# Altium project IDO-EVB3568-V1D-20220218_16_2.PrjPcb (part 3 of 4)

## Sheet P16.SchDoc
size 297 x 209 mm
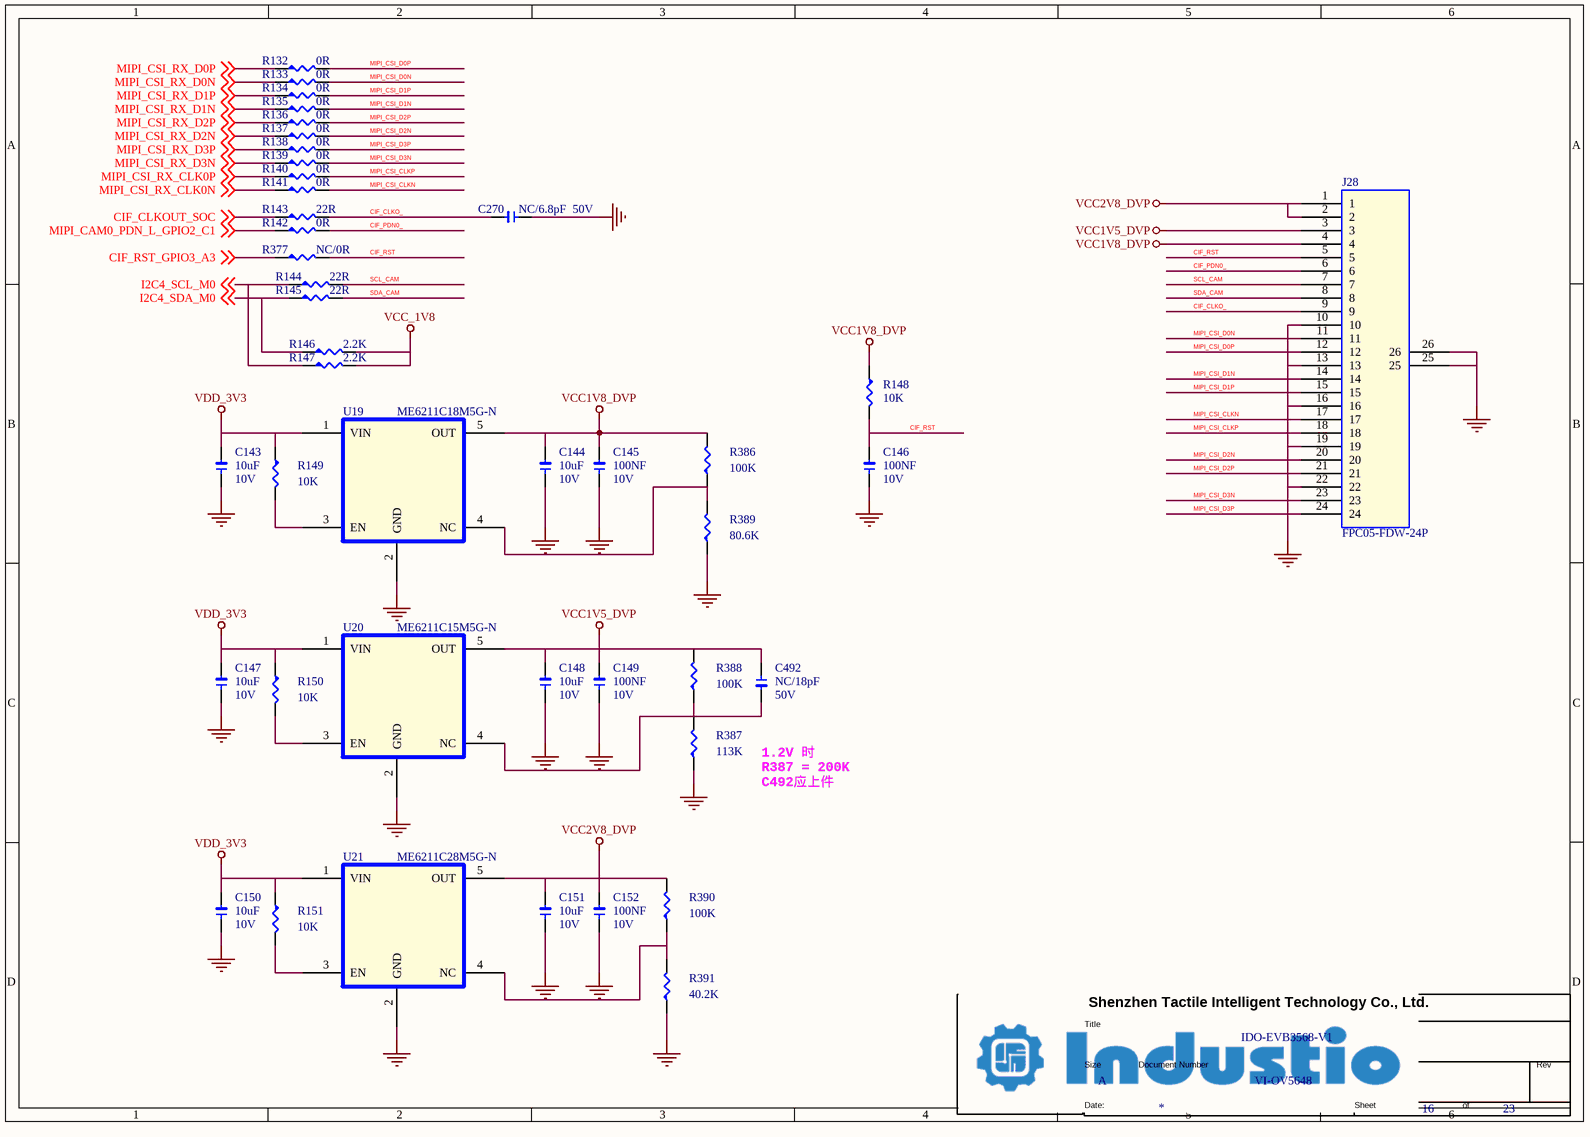
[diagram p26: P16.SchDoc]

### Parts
(Parts that share a designator on the sheet are numbered #1, #2 ... from top to bottom, then left to right.)
*#16  Doc: VI-OV5648  Title: IDO-EVB3568-V1  Page Size: A  Page Number: 16  Page Count: 23  (hidden comment: TitleBlock1)  (graphical)
C143  10uF  DSC2: 10V  [1206]
C144  10uF  DSC2: 10V  [1206]
C145  100NF  DSC2: 10V  [1206]
C146  100NF  DSC2: 10V  [1206]
C147  10uF  DSC2: 10V  [1206]
C148  10uF  DSC2: 10V  [1206]
C149  100NF  DSC2: 10V  [1206]
C150  10uF  DSC2: 10V  [1206]
C151  10uF  DSC2: 10V  [1206]
C152  100NF  DSC2: 10V  [1206]
C270  NC/6.8pF  DSC2: 50V  [1206]
C492  NC/18pF  DSC2: 50V  [1206]
J28  FPC05-FDW-24P  [FPC05-ZDW-24P]
R132  0R  [R0402L]
R133  0R  [R0402L]
R134  0R  [R0402L]
R135  0R  [R0402L]
R136  0R  [R0402L]
R137  0R  [R0402L]
R138  0R  [R0402L]
R139  0R  [R0402L]
R140  0R  [R0402L]
R141  0R  [R0402L]
R142  0R  [R0402L]
R143  22R  [R0402L]
R144  22R  [R0402L]
R145  22R  [R0402L]
R146  2.2K  [R0402L]
R147  2.2K  [R0402L]
R148  10K  [R0402L]
R149  10K  [R0402L]
R150  10K  [R0402L]
R151  10K  [R0402L]
R377  NC/0R  [R0402L]
R386  100K  [R0402L]
R387  113K  [R0402L]
R388  100K  [R0402L]
R389  80.6K  [R0402L]
R390  100K  [R0402L]
R391  40.2K  [R0402L]
U19  ME6211C18M5G-N  [SOT23-5]
U20  ME6211C15M5G-N  [SOT23-5]
U21  ME6211C28M5G-N  [SOT23-5]

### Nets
GND: C143.1 C144.1 C145.1 C146.1 C147.1 C148.1 C149.1 C150.1 C151.1 C152.1 C270.1 J28.10 J28.13 J28.16 J28.19 J28.22 J28.25 J28.26 R387.1 R389.1 R391.1 U19.2(GND) U20.2(GND) U21.2(GND)
VCC1V5_DVP: C148.2 C149.2 C492.1 J28.3 R388.2 U20.5(OUT)
VCC1V8_DVP: C144.2 C145.2 J28.4 R148.1 R386.2 U19.5(OUT)
VCC2V8_DVP: C151.2 C152.2 J28.1 J28.2 R390.2 U21.5(OUT)
VCC_1V8: R146.2 R147.2
VDD_3V3: C143.2 C147.2 C150.2 R149.1 R150.1 R151.1 U19.1(VIN) U20.1(VIN) U21.1(VIN)
CIF_CLKO_: C270.2 J28.9 R143.2
CIF_CLKOUT_SOC: R143.1 ; off-sheet CIF_CLKOUT_SOC  [project net CIF_CLKOUT/EBC_GDCLK/PWM11_IR_M1/GPIO4_C0_d]
CIF_PDN0_: J28.6 R142.2
CIF_RST: C146.2 J28.5 R148.2 R377.2
CIF_RST_GPIO3_A3: R377.1 ; off-sheet CIF_RST_GPIO3_A3  [project net LCDC_D10/VOP_BT1120_D2/GMAC1_TXD3_M0/I2S3_SCLK_M0/SDMMC2_D2_M1/GPIO3_A3_d]
I2C4_SCL_M0: R144.1 R147.1 ; off-sheet I2C4_SCL_M0  [project net I2C4_SCL_M0/EBC_GDOE/ETH1_REFCLKO_25M_M1/SPI3_CLK_M0/I2S2_SDO_M1/GPIO4_B3_d]
I2C4_SDA_M0: R145.1 R146.1 ; off-sheet I2C4_SDA_M0  [project net I2C4_SDA_M0/EBC_VCOM/GMAC1_RXER_M1/SPI3_MOSI_M0/I2S2_SDI_M1/GPIO4_B2_d]
MIPI_CAM0_PDN_L_GPIO2_C1: R142.1 ; off-sheet MIPI_CAM0_PDN_L_GPIO2_C1  [project net I2S2_MCLK_M0/ETH0_REFCLKO_25M/UART7_RTSn_M0/SPI2_CLK_M0/GPIO2_C1_d]
MIPI_CSI_CLKN: J28.17 R141.2
MIPI_CSI_CLKP: J28.18 R140.2
MIPI_CSI_D0N: J28.11 R133.2
MIPI_CSI_D0P: J28.12 R132.2
MIPI_CSI_D1N: J28.14 R135.2
MIPI_CSI_D1P: J28.15 R134.2
MIPI_CSI_D2N: J28.20 R137.2
MIPI_CSI_D2P: J28.21 R136.2
MIPI_CSI_D3N: J28.23 R139.2
MIPI_CSI_D3P: J28.24 R138.2
MIPI_CSI_RX_CLK0N: R141.1 ; off-sheet MIPI_CSI_RX_CLK0N  [project net MIPI_CSI_RX_CLK0N/PCIE30_REFCLKN_IN]
MIPI_CSI_RX_CLK0P: R140.1 ; off-sheet MIPI_CSI_RX_CLK0P  [project net MIPI_CSI_RX_CLK0P/PCIE30_REFCLKP_IN]
MIPI_CSI_RX_D0N: R133.1 ; off-sheet MIPI_CSI_RX_D0N  [project net MIPI_CSI_RX_D0N/PCIE30_TX0N]
MIPI_CSI_RX_D0P: R132.1 ; off-sheet MIPI_CSI_RX_D0P  [project net MIPI_CSI_RX_D0P/PCIE30_TX0P]
MIPI_CSI_RX_D1N: R135.1 ; off-sheet MIPI_CSI_RX_D1N  [project net MIPI_CSI_RX_D1N/PCIE30_TX1N]
MIPI_CSI_RX_D1P: R134.1 ; off-sheet MIPI_CSI_RX_D1P  [project net MIPI_CSI_RX_D1P/PCIE30_TX1P]
MIPI_CSI_RX_D2N: R137.1 ; off-sheet MIPI_CSI_RX_D2N  [project net MIPI_CSI_RX_D2N/PCIE30_RX0N]
MIPI_CSI_RX_D2P: R136.1 ; off-sheet MIPI_CSI_RX_D2P  [project net MIPI_CSI_RX_D2P/PCIE30_RX0P]
MIPI_CSI_RX_D3N: R139.1 ; off-sheet MIPI_CSI_RX_D3N  [project net MIPI_CSI_RX_D3N/PCIE30_RX1N]
MIPI_CSI_RX_D3P: R138.1 ; off-sheet MIPI_CSI_RX_D3P  [project net MIPI_CSI_RX_D3P/PCIE30_RX1P]
SCL_CAM: J28.7 R144.2
SDA_CAM: J28.8 R145.2
NetC492_2: C492.2 R387.2 R388.1 U20.4(NC)
NetR149_2: R149.2 U19.3(EN)
NetR150_2: R150.2 U20.3(EN)
NetR151_2: R151.2 U21.3(EN)
NetR386_1: R386.1 R389.2 U19.4(NC)
NetR390_1: R390.1 R391.2 U21.4(NC)

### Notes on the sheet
- 1.2V 时
  R387 = 200K
  C492应上件

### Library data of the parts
C143 C144 C147 C148 C150 C151 = C-0603: Manufacture: 三星¦国巨¦村田; Part Name: 贴片电容; Part Number: C020102120071; ID: 71; DSC3: X5R; DSC1: ±20%; ERP Number: 1010200076; PCB Footprint: C0603L
C145 C146 C152 = C-0402_Dup1: Part Number: C020102120060; Part Name: 贴片电容; Manufacture: 三星¦国巨¦村田; DSC1: ±10%; DSC3: X7R; ID: 60; PCB Footprint: C0402L
C149 = C-0402_Dup1: Manufacture: 三星¦国巨¦村田; Part Name: 贴片电容; Part Number: C020102120060; ID: 60; DSC3: X7R; DSC1: ±10%; PCB Footprint: C0402L
C270 = C-0402_Dup1: Manufacture: 三星¦国巨¦村田; Part Name: 贴片电容; Part Number: C020102120018; PCB Footprint: C0402L; ID: 18; DSC3: C0G; DSC1: ±0.25PF; ERP Number: 1010200056
C492 = C-0402_Dup1: Part Number: C020102120027; Part Name: 贴片电容; Manufacture: 三星¦国巨¦村田; ERP Number: 1010200091; DSC1: ±5%; DSC3: C0G; ID: 27; PCB Footprint: C0402L
J28 = J-FPC05-24P: Part Name: FPC座; DSC1: 24P; DSC2: 0.5mm间距; DSC3: 下接 翻盖 卧贴; DSC4: H=2mm; DSC5: 镀锡; DSC6: X05C2024TZ(星坤); ID: 37
R132-R141 R377 = R-0402_Dup1: Part Number: C011002080413; Part Name: 贴片电阻; ID: 413; DSC2: 1/16W; DSC1: ±1%
R142 = R-0402_Dup1: Part Name: 贴片电阻; Part Number: C011002080413; DSC1: ±1%; DSC2: 1/16W; ID: 413
R143 = R-0402_Dup1: Part Name: 贴片电阻; Part Number: C011002080552; DSC1: ±1%; DSC2: 1/16W; ID: 552
R144 R145 = R-0402_Dup1: Part Number: C011002080552; Part Name: 贴片电阻; ID: 552; DSC2: 1/16W; DSC1: ±1%
R146 = R-0402_Dup1: Part Number: C011002080778; Part Name: 贴片电阻; ID: 778; DSC2: 1/16W; DSC1: ±1%
R147 = R-0402_Dup1: Part Name: 贴片电阻; Part Number: C011002080778; DSC1: ±1%; DSC2: 1/16W; ID: 778
R148-R151 = R-0402_Dup1: Part Number: C011002080856; Part Name: 贴片电阻; ID: 856; DSC2: 1/16W; DSC1: ±1%; ERP Number: 1010200140
R386 R388 R390 = R-0402: Part Number: C011002080976; Part Name: 贴片电阻; DSC2: 1/16W; DSC1: ±1%; ERP Number: 1010200137
R387 = R-0402: Part Number: C011002080981; Part Name: 贴片电阻; DSC2: 1/16W; DSC1: ±1%
R389 = R-0402: Part Name: 贴片电阻; Part Number: C011002080964; ERP Number: 1010200373; DSC1: ±1%; DSC2: 1/16W
R391 = R-0402: Part Name: 贴片电阻; Part Number: C011002080926; ERP Number: 1010200179; DSC1: ±1%; DSC2: 1/16W
U19 = U-ME6211C18M5G-N: Manufacture: 南京微盟; Part Number: C070102400003; Part Name: LDO; ID: 3; DSC5: Iq=30uA; DSC4: -62db(1K); DSC3: Io=500mA; DSC2: Vo=1.8V; DSC1: Vi=1.5-6.5V
U20 = U-ME6211C15M5G-N: Manufacture: 南京微盟; Part Number: C070107223911; Part Name: LDO; ID: 27; DSC5: Iq=30uA; DSC4: -62db(1K); DSC3: Io=300mA; DSC2: Vo=1.5V; DSC1: Vi=1.5-6.5V
U21 = U-ME6211C28M5G-N: Part Name: LDO; Part Number: C070102400018; Manufacture: 南京微盟; DSC1: Vi=1.5-6.5V; DSC2: Vo=2.8V; DSC3: Io=500mA; DSC4: -62db(1K); DSC5: Iq=30uA; ID: 18

## Sheet P17.SchDoc
size 420 x 297 mm
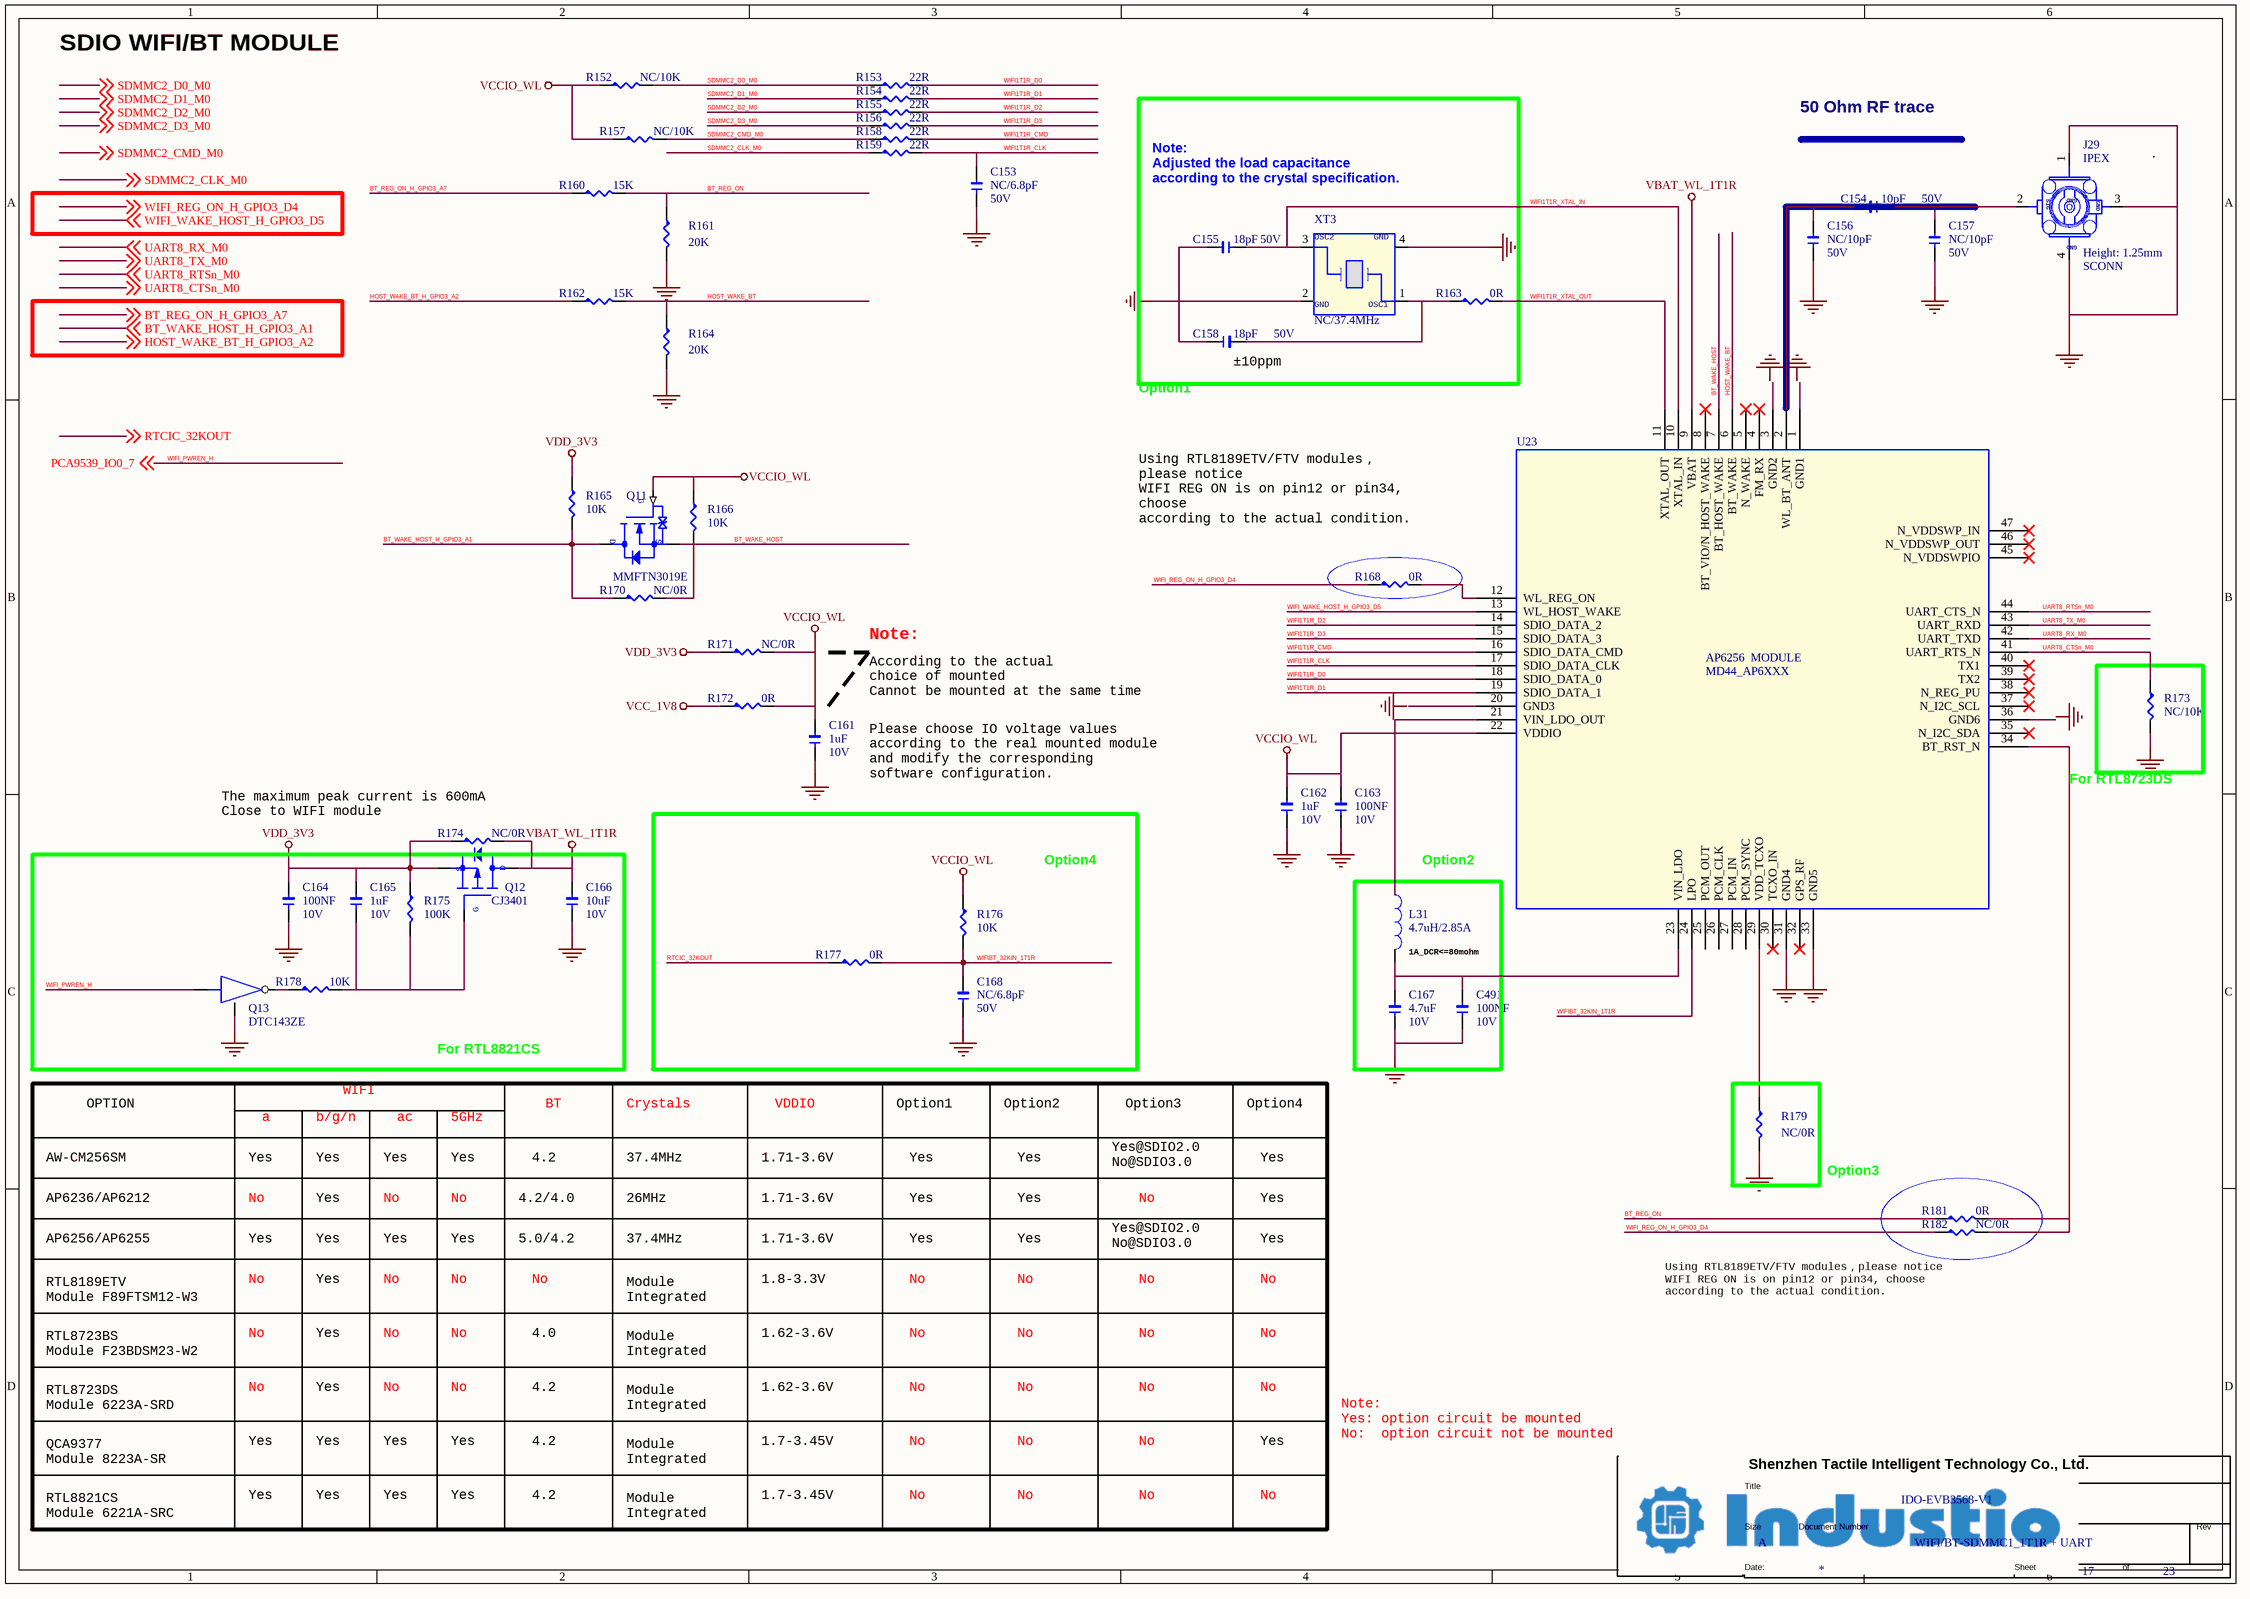
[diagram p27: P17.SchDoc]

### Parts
(Parts that share a designator on the sheet are numbered #1, #2 ... from top to bottom, then left to right.)
*#17  Doc: WIFI/BT-SDMMC1_1T1R + UART  Title: IDO-EVB3568-V1  Page Size: A  Page Number: 17  Page Count: 23  (hidden comment: TitleBlock1)  (graphical)
C153  NC/6.8pF  DSC2: 50V  [1206]
C154  10pF  DSC2: 50V  [1206]
C155  18pF  DSC2: 50V  [1206]
C156  NC/10pF  DSC2: 50V  [1206]
C157  NC/10pF  DSC2: 50V  [1206]
C158  18pF  DSC2: 50V  [1206]
C161  1uF  DSC2: 10V  [1206]
C162  1uF  DSC2: 10V  [1206]
C163  100NF  DSC2: 10V  [1206]
C164  100NF  DSC2: 10V  [1206]
C165  1uF  DSC2: 10V  [1206]
C166  10uF  DSC2: 10V  [1206]
C167  4.7uF  DSC2: 10V  [1206]
C168  NC/6.8pF  DSC2: 50V  [1206]
C491  100NF  DSC2: 10V  [1206]
J29  IPEX  Height: 1.25mm  Material: SCONN  [IPEX-20279-001E]
L31  4.7uH/2.85A  [L4040]
Q11  MMFTN3019E  [SOT523]
Q12  CJ3401  [SOT23]
Q13  DTC143ZE  [SOT523]
R152  NC/10K  [R0402L]
R153  22R  [R0402L]
R154  22R  [R0402L]
R155  22R  [R0402L]
R156  22R  [R0402L]
R157  NC/10K  [R0402L]
R158  22R  [R0402L]
R159  22R  [R0402L]
R160  15K  [R0402L]
R161  20K  [R0402L]
R162  15K  [R0402L]
R163  0R  [R0402L]
R164  20K  [R0402L]
R165  10K  [R0402L]
R166  10K  [R0402L]
R168  0R  [R0402L]
R170  NC/0R  [R0402L]
R171  NC/0R  [R0402L]
R172  0R  [R0402L]
R173  NC/10K  [R0402L]
R174  NC/0R  [R0805L]
R175  100K  [R0402L]
R176  10K  [R0402L]
R177  0R  [R0402L]
R178  10K  [R0402L]
R179  NC/0R  [R0402L]
R181  0R  [R0402L]
R182  NC/0R  [R0402L]
U23  AP6256  MODULE  [MD44_AP6XXX]
XT3  NC/37.4MHz  [xtal_32x25_4p]

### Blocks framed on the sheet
±10ppm: C155 C158 R163 XT3
For RTL8821CS: C164-C166 Q12 Q13 R175 R178
Option4: C168 R176 R177
Option2: C167 C491 L31

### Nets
GND: C153.1 C155.2 C156.1 C157.1 C158.1 C161.1 C162.1 C163.1 C164.1 C166.1 C167.1 C168.1 C491.1 J29.1(GND1) J29.3(GND2) J29.4(GND3) Q13.2 R161.2 R164.2 R173.2 R179.2 U23.31(GND4) U23.33(GND5) XT3.2 XT3.4
VBAT_WL_1T1R: C166.2 Q12.3(DRAIN) R174.2 U23.9(VBAT)
VCC_1V8: R172.1
VCCIO_WL: C161.2 C162.2 C163.2 Q11.1(GATE) R152.1 R157.1 R166.1 R171.2 R172.2 R176.1 U23.22(VDDIO)
VDD_3V3: C164.2 C165.2 Q12.2(SOURCE) R165.1 R171.1 R174.1 R175.1
BT_REG_ON: R160.2 R161.1 R181.1
BT_REG_ON_H_GPIO3_A7: R160.1 ; off-sheet BT_REG_ON_H_GPIO3_A7
BT_WAKE_HOST: Q11.2(SOURCE) R166.2 R170.2 U23.7(BT_HOST_WAKE)
BT_WAKE_HOST_H_GPIO3_A1: Q11.3(DRAIN) R165.2 R170.1 ; off-sheet BT_WAKE_HOST_H_GPIO3_A1
HOST_WAKE_BT: R162.2 R164.1 U23.6(BT_WAKE)
HOST_WAKE_BT_H_GPIO3_A2: R162.1 ; off-sheet HOST_WAKE_BT_H_GPIO3_A2
PCA9539_IO0_7: Q13.1 ; off-sheet PCA9539_IO0_7  [also labelled WIFI_PWREN_H]
RTCIC_32KOUT: R177.1 ; off-sheet RTCIC_32KOUT  [project net RTC_32KOUT]
SDMMC2_CLK_M0: R159.1 ; off-sheet SDMMC2_CLK_M0  [project net CIF_D5/EBC_SDDO5/SDMMC2_CLK_M0/I2S1_SDI1_M1/VOP_BT656_D5_M1/GPIO3_D3_d]
SDMMC2_CMD_M0: R157.2 R158.1 ; off-sheet SDMMC2_CMD_M0  [project net CIF_D4/EBC_SDDO4/SDMMC2_CMD_M0/I2S1_SDI0_M1/VOP_BT656_D4_M1/GPIO3_D2_d]
SDMMC2_D0_M0: R152.2 R153.1 ; off-sheet SDMMC2_D0_M0  [project net CIF_D0/EBC_SDDO0/SDMMC2_D0_M0/I2S1_MCLK_M1/VOP_BT656_D0_M1/GPIO3_C6_d]
SDMMC2_D1_M0: R154.1 ; off-sheet SDMMC2_D1_M0  [project net CIF_D1/EBC_SDDO1/SDMMC2_D1_M0/I2S1_SCLK_TX_M1/VOP_BT656_D1_M1/GPIO3_C7_d]
SDMMC2_D2_M0: R155.1 ; off-sheet SDMMC2_D2_M0  [project net CIF_D2/EBC_SDDO2/SDMMC2_D2_M0/I2S1_LRCK_TX_M1/VOP_BT656_D2_M1/GPIO3_D0_d]
SDMMC2_D3_M0: R156.1 ; off-sheet SDMMC2_D3_M0  [project net CIF_D3/EBC_SDDO3/SDMMC2_D3_M0/I2S1_SDO0_M1/VOP_BT656_D3_M1/GPIO3_D1_d]
UART8_CTSn_M0: R173.1 U23.41(UART_RTS_N) ; off-sheet UART8_CTSn_M0  [project net SDMMC1_DET/I2C4_SCL_M1/UART8_CTSn_M0/CAN2_TX_M1/GPIO2_B2_u]
UART8_RTSn_M0: U23.44(UART_CTS_N) ; off-sheet UART8_RTSn_M0  [project net SDMMC1_PWREN/I2C4_SDA_M1/UART8_RTSn_M0/CAN2_RX_M1/GPIO2_B1_d]
UART8_RX_M0: U23.42(UART_TXD) ; off-sheet UART8_RX_M0  [project net CLK32K_OUT1/UART8_RX_M0/SPI1_CS1_M0/GPIO2_C6_d]
UART8_TX_M0: U23.43(UART_RXD) ; off-sheet UART8_TX_M0  [project net I2S2_SDI_M0/GMAC0_RXER/UART8_TX_M0/SPI2_CS1_M0/GPIO2_C5_d]
WIFI1T1R_CLK: C153.2 R159.2 U23.17(SDIO_DATA_CLK)
WIFI1T1R_CMD: R158.2 U23.16(SDIO_DATA_CMD)
WIFI1T1R_D0: R153.2 U23.18(SDIO_DATA_0)
WIFI1T1R_D1: R154.2 U23.19(SDIO_DATA_1)
WIFI1T1R_D2: R155.2 U23.14(SDIO_DATA_2)
WIFI1T1R_D3: R156.2 U23.15(SDIO_DATA_3)
WIFI1T1R_XTAL_IN: C155.1 U23.10(XTAL_IN) XT3.3
WIFI1T1R_XTAL_OUT: R163.2 U23.11(XTAL_OUT)
WIFI_REG_ON_H_GPIO3_D4: R168.1 R182.1 ; off-sheet WIFI_REG_ON_H_GPIO3_D4  [project net CIF_D6/EBC_SDDO6/SDMMC2_DET_M0/I2S1_SDI2_M1/VOP_BT656_D6_M1/GPIO3_D4_d]
WIFI_WAKE_HOST_H_GPIO3_D5: U23.13(WL_HOST_WAKE) ; off-sheet WIFI_WAKE_HOST_H_GPIO3_D5  [project net CIF_D7/EBC_SDDO7/SDMMC2_PWREN_M0/I2S1_SDI3_M1/VOP_BT656_D7_M1/GPIO3_D5_d]
WIFIBT_32KIN_1T1R: C168.2 R176.2 R177.2 U23.24(LPO)
NetC154_1: C154.1 C157.2 J29.2(SIG)
NetC154_2: C154.2 C156.2 U23.2(WL_BT_ANT)
NetC158_2: C158.2 R163.1 XT3.1
NetC165_1: C165.1 Q12.1(GATE) R175.2 R178.2
NetC167_2: C167.2 C491.2 L31.2 U23.23(VIN_LDO)
NetL31_1: L31.1 U23.21(VIN_LDO_OUT)
NetQ13_3: Q13.3 R178.1
NetR168_2: R168.2 U23.12(WL_REG_ON)
NetR179_1: R179.1 U23.29(VDD_TCXO)
NetR181_2: R181.2 R182.2 U23.34(BT_RST_N)

Not connected (* = marked no-connect by the designer): U23 1(GND1) 3(GND2) 4(FM_RX)* 5(N_WAKE)* 8(BT_VIO/N_HOST_WAKE)* 20(GND3) 25(PCM_OUT) 26(PCM_CLK) 27(PCM_IN) 28(PCM_SYNC) 30(TCXO_IN)* 32(GPS_RF)* 35(N_I2C_SDA)* 36(GND6) 37(N_I2C_SCL)* 38(N_REG_PU)* 39(TX2)* 40(TX1)* 45(N_VDDSWPIO)* 46(N_VDDSWP_OUT)* 47(N_VDDSWP_IN)*

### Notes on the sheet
- SDIO WIFI/BT MODULE
- 50 Ohm RF trace
- Note:
  Adjusted the load capacitance
  according to the crystal specification.
- (near C158) Option1
- (near U23) Using RTL8189ETV/FTV modules，
  please notice
  WIFI REG ON is on pin12 or pin34,
  choose
  according to the actual condition.
- According to the actual
  choice of mounted
  Cannot be mounted at the same time
- Note:
- (near C162) Please choose IO voltage values
  according to the real mounted module
  and modify the corresponding
  software configuration.
- (near R174) The maximum peak current is 600mA
  Close to WIFI module
- For RTL8723DS
- (near L31) 1A_DCR<=80mohm
- OPTION
- a
- b/g/n
- WIFI
- ac
- 5GHz
- BT
- Crystals
- VDDIO
- Option1
- Option2
- Yes@SDIO2.0
  No@SDIO3.0
- Option3
- Option4
- AP6236/AP6212
- AW-CM256SM
- No
- Yes
- 4.2/4.0
- 4.2
- 26MHz
- 37.4MHz
- 1.71-3.6V
- AP6256/AP6255
- RTL8189ETV
  Module F89FTSM12-W3
- 5.0/4.2
- Module
  Integrated
- Using RTL8189ETV/FTV modules，please notice
  WIFI REG ON is on pin12 or pin34, choose
  according to the actual condition.
- RTL8723BS
  Module F23BDSM23-W2
- 4.0
- 1.62-3.6V
- 1.8-3.3V
- RTL8723DS
  Module 6223A-SRD
- (near *#17) Note:
  Yes: option circuit be mounted
  No:  option circuit not be mounted
- QCA9377
  Module 8223A-SR
- 1.7-3.45V
- RTL8821CS
  Module 6221A-SRC
- Labels drawn without touching a wire or pin: GND

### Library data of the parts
C153 = C-0402_Dup1: as C270 on sheet P16
C154 = C-0402_Dup1: Part Number: C020102120021; Part Name: 贴片电容; Manufacture: 三星¦国巨¦村田; PCB Footprint: C0402L; ERP Number: 1010200151; DSC1: ±5%; DSC3: C0G; ID: 21
C155 = C-0402_Dup1: as C492 on sheet P16
C156 C157 = C-0402_Dup1: Manufacture: 三星¦国巨¦村田; Part Name: 贴片电容; Part Number: C020102120021; PCB Footprint: C0402L; ID: 21; DSC3: C0G; DSC1: ±5%; ERP Number: 1010200151
C158 = C-0402_Dup1: Manufacture: 三星¦国巨¦村田; Part Name: 贴片电容; Part Number: C020102120027; ID: 27; DSC3: C0G; DSC1: ±5%; ERP Number: 1010200091; PCB Footprint: C0402L
C161 = C-0402_Dup1: Part Number: C020102120064; Part Name: 贴片电容; Manufacture: 三星¦国巨¦村田; PCB Footprint: C0402L; ERP Number: 1010200054; DSC1: ±10%; DSC3: X5R; ID: 64
C162 C165 = C-0402_Dup1: Manufacture: 三星¦国巨¦村田; Part Name: 贴片电容; Part Number: C020102120064; PCB Footprint: C0402L; ID: 64; DSC3: X5R; DSC1: ±10%; ERP Number: 1010200054
C163 C164 C491 = C-0402_Dup1: Manufacture: 三星¦国巨¦村田; Part Name: 贴片电容; Part Number: C020102120060; PCB Footprint: C0402L; ID: 60; DSC3: X7R; DSC1: ±10%
C166 = C-0603: Part Number: C020102120071; Part Name: 贴片电容; Manufacture: 三星¦国巨¦村田; PCB Footprint: C0603L; ERP Number: 1010200076; DSC1: ±20%; DSC3: X5R; ID: 71
C167 = C-0402_Dup1: Manufacture: 三星¦国巨¦村田; Part Name: 贴片电容; Part Number: C020102120067; PCB Footprint: C0402L; ID: 67; DSC3: X5R; DSC1: ±20%
C168 = C-0402_Dup1: Part Number: C020102120018; Part Name: 贴片电容; Manufacture: 三星¦国巨¦村田; PCB Footprint: C0402L; ERP Number: 1010200056; DSC1: ±0.25PF; DSC3: C0G; ID: 18
J29 = RF-IPEX-20279: SMD micro Coaxial Connector Receptacle vertial; Part_Name: MHF-20279; Part Name: IPEX座; Part Number: J110103040001; ID: 1; DSC2: 贴片; DSC1: IPEX-20279-001E-01 板端贴片天线座 U.LF接头
L31 = L-IND: Part Name: 功率电感; Part Number: C060202340021; Manufacture: 顺络; ERP Number: 1010200405; DSC1: ±20%; DSC2: Isat=4.0A; DSC3: Irms=2.85A; DSC4: 108mΩ; DSC5: 4.0*4.0*2.0mm; DSC6: WPN4020H4R7MT(顺络)
Q11 = N-MOS-Q: Manufacture: 先科; Part Name: N-MOS; Part Number: C030202190004; ID: 4; DSC5: pd=150mW; DSC4: Vgs=±20V; DSC3: Vgs(th)=1.5V; DSC2: Id=100mA; DSC1: Vds=30V; ERP Number: 1010800011
Q12 = P-MOS: Part Number: C030202190001; Manufacture: 长电; ERP Number: 1010800001; DSC1: Vds=-30V; DSC2: Id=-4.2A; DSC3: Vgs(th)=1.3V; DSC4: Vgs=±12V; DSC5: pd=350mW; ID: 1
Q13 = S-NPN: Manufacture: CJ江苏长电; Part Number: BJ00G1100000; LC Number: C78593; DSC1: 数字三极管,NPN - 预偏压,Ic=100mA; Type Name: 数字三极管; ERP Number: 0; ID: 2
R152 R157 R165 R166 = R-0402_Dup1: as R148-R151 on sheet P16
R153 = R-0402_Dup1: as R144 on sheet P16
R154-R156 R158 R159 = R-0402_Dup1: as R143 on sheet P16
R160 R162 = R-0402_Dup1: Part Number: C011002080875; Part Name: 贴片电阻; ID: 875; DSC2: 1/16W; DSC1: ±1%; ERP Number: 1010200458
R161 R164 = R-0402_Dup1: Part Number: C011002080889; Part Name: 贴片电阻; ID: 889; DSC2: 1/16W; DSC1: ±1%; ERP Number: 1010200333
R163 R172 R177 R181 R182 = R-0402_Dup1: as R132-R141 on sheet P16
R168 R170 R171 R179 = R-0402_Dup1: as R142 on sheet P16
R173 R176 R178 = R-0402_Dup1: Part Name: 贴片电阻; Part Number: C011002080856; ERP Number: 1010200140; DSC1: ±1%; DSC2: 1/16W; ID: 856
R174 = R-0805: Part Name: 贴片电阻; Part Number: C011002081448; ERP Number: 1010200199; DSC1: ±1%; DSC2: 1/8W; ID: 1,448
R175 = R-0402_Dup1: Part Name: 贴片电阻; Part Number: C011002080976; ERP Number: 1010200137; DSC1: ±1%; DSC2: 1/16W; ID: 976
U23 = MODULE_AP6XXX: WiFi+Bluetooth 4.0(HS)+FM Rx; Manufacturer: Ampak（正基科技）; RK PN: AP6335; Priority: A
XT3 = XTAL-4P: Manufacture: 爱普生; Part Name: 贴片无源晶振; CLASS: IC; ID: 13; DSC5: 3.2*2.5mm 4P; DSC4: -40℃~+85℃; DSC3: 12pF; DSC2: ±10ppm; DSC1: 60Ω

## Sheet P18.SchDoc
size 594 x 420 mm
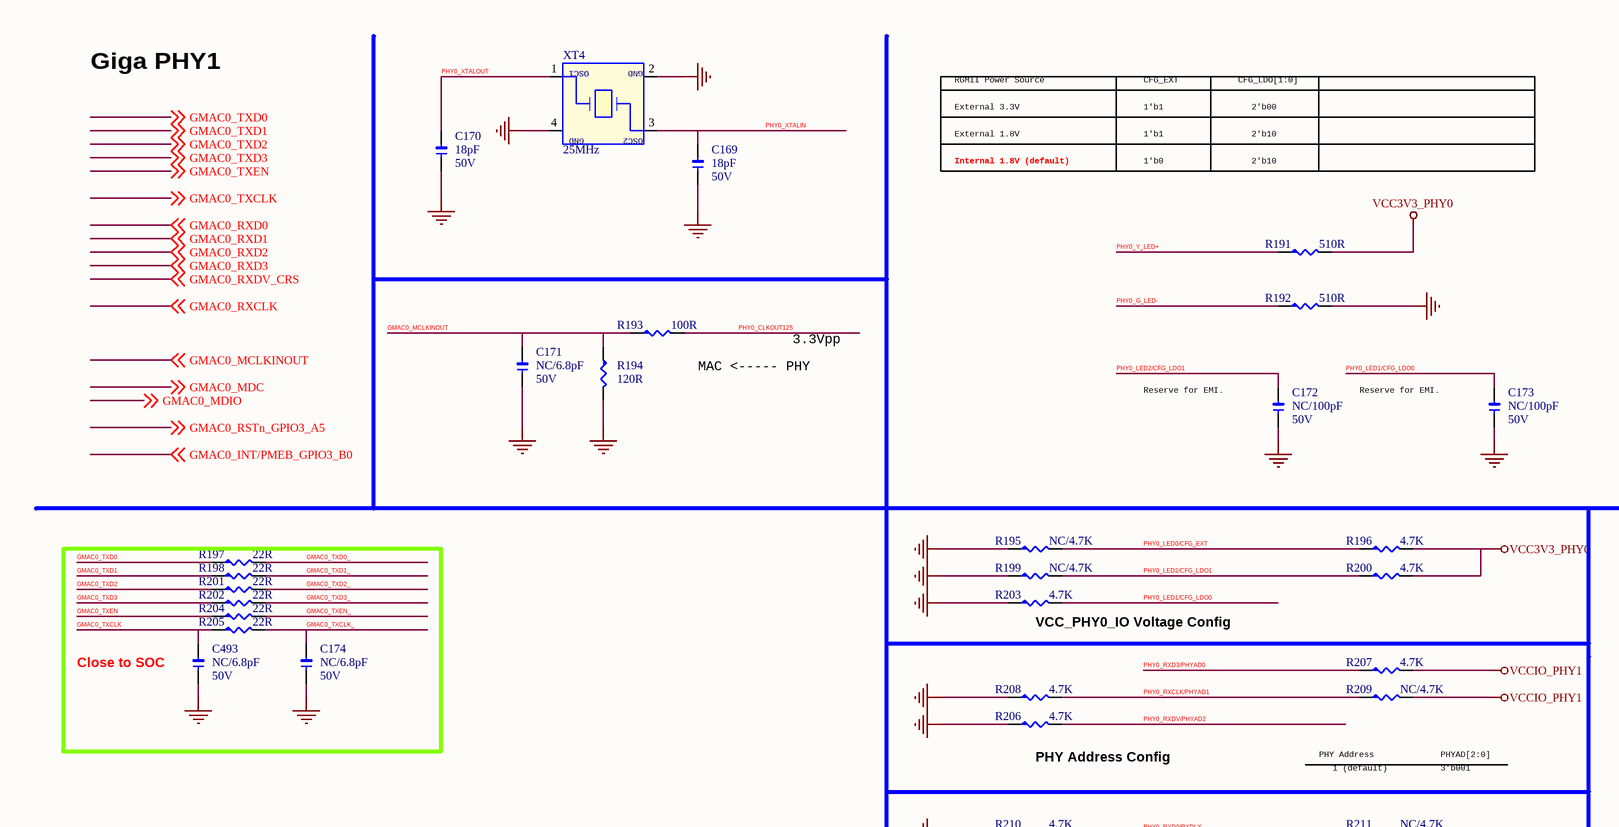
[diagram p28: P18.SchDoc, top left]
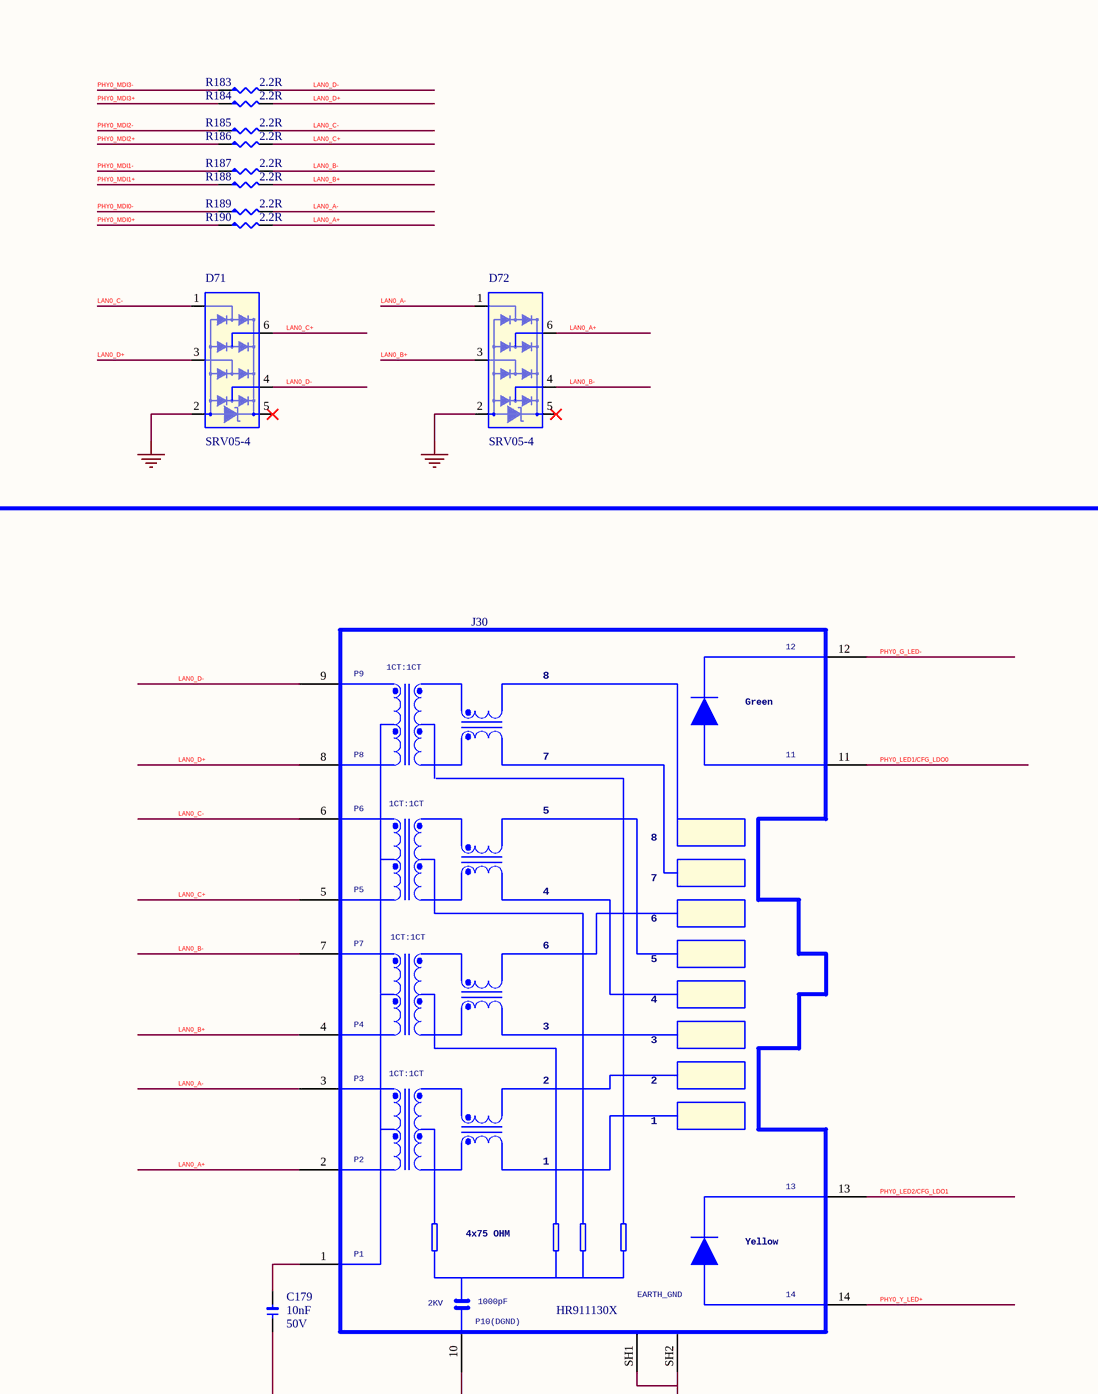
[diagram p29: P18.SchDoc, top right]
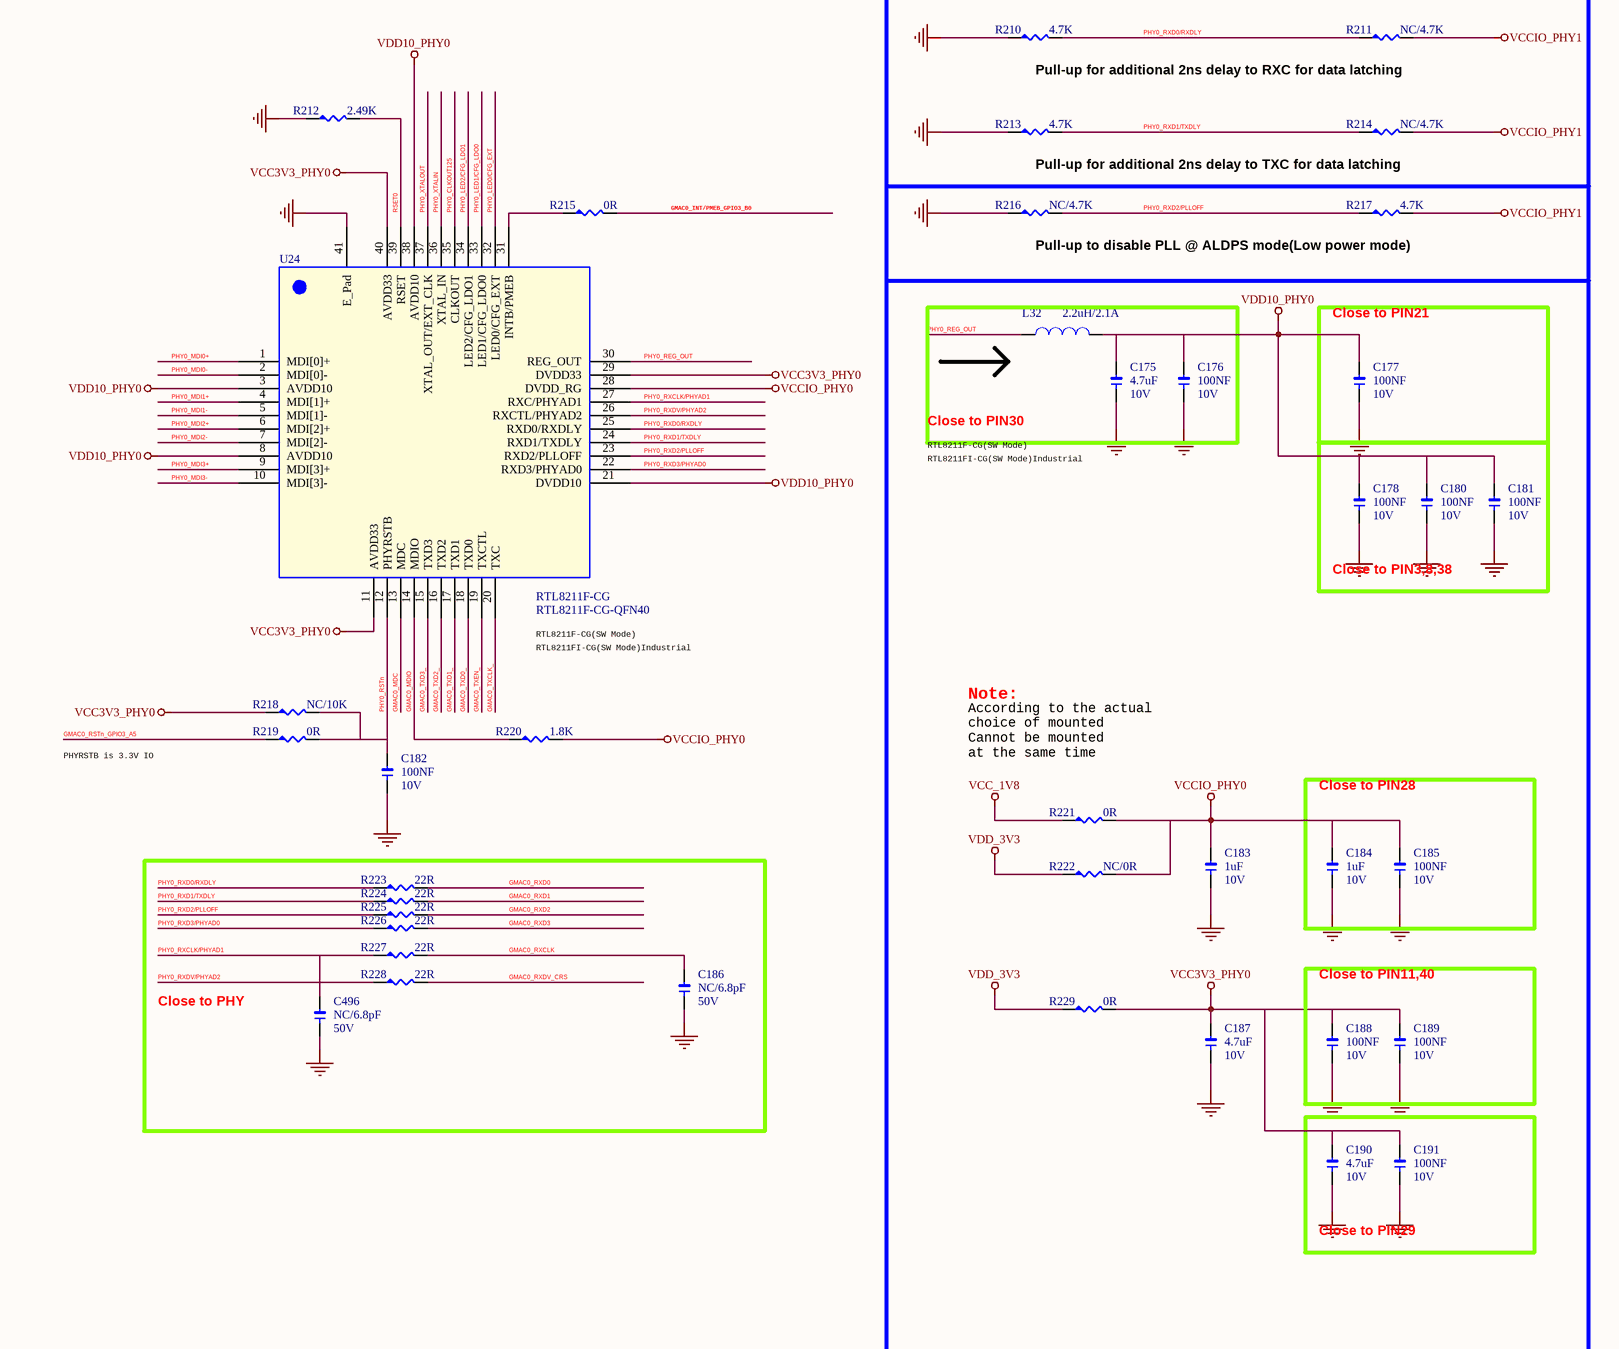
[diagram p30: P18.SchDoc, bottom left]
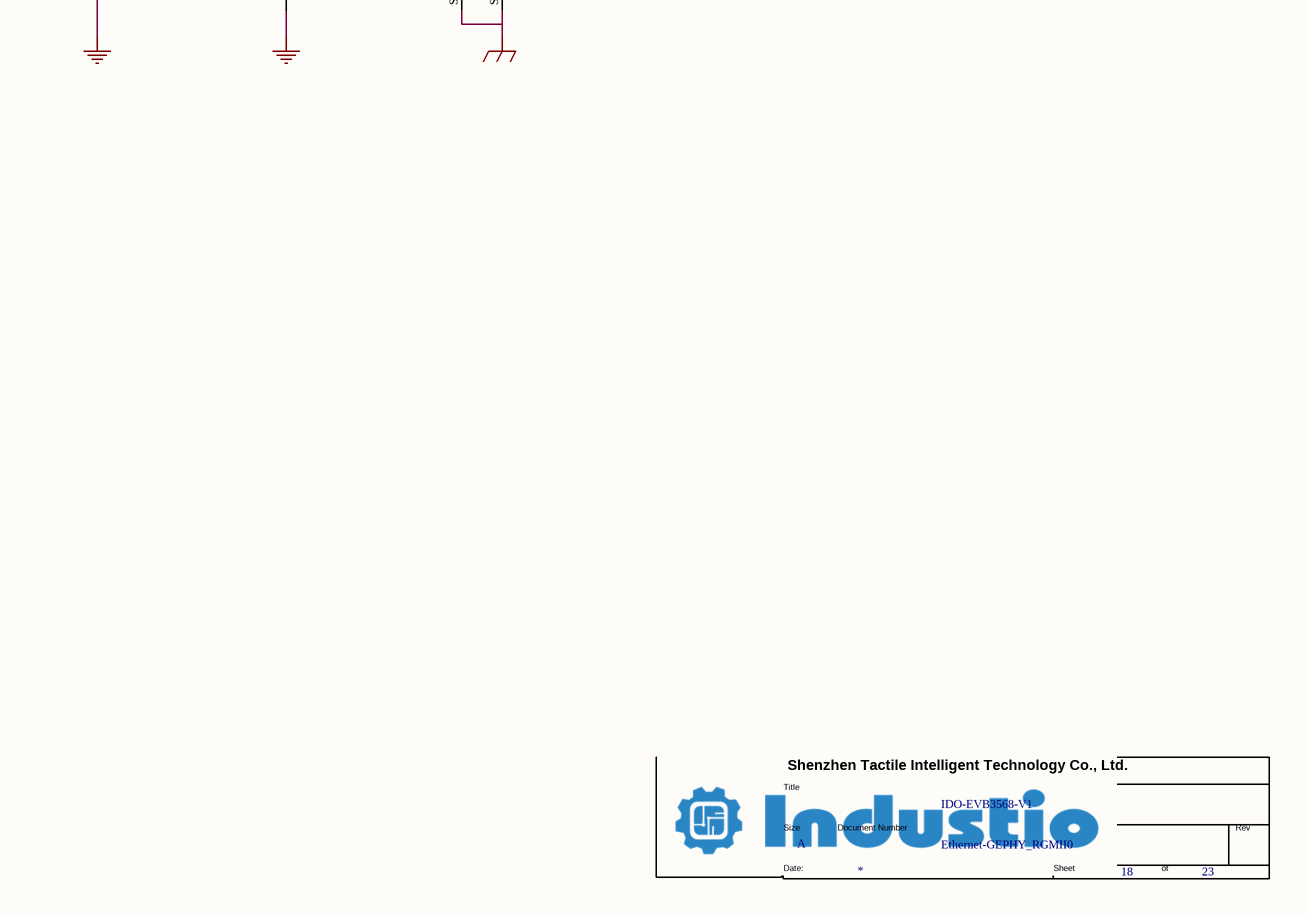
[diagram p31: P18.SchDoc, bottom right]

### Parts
(Parts that share a designator on the sheet are numbered #1, #2 ... from top to bottom, then left to right.)
*#18  Doc: Ethernet-GEPHY_RGMII0  Title: IDO-EVB3568-V1  Page Size: A  Page Number: 18  Page Count: 23  (hidden comment: TitleBlock1)  (graphical)
C169  18pF  DSC2: 50V  [1206]
C170  18pF  DSC2: 50V  [1206]
C171  NC/6.8pF  DSC2: 50V  [1206]
C172  NC/100pF  DSC2: 50V  [1206]
C173  NC/100pF  DSC2: 50V  [1206]
C174  NC/6.8pF  DSC2: 50V  [1206]
C175  4.7uF  DSC2: 10V  [1206]
C176  100NF  DSC2: 10V  [1206]
C177  100NF  DSC2: 10V  [1206]
C178  100NF  DSC2: 10V  [1206]
C179  10nF  DSC2: 50V  [1206]
C180  100NF  DSC2: 10V  [1206]
C181  100NF  DSC2: 10V  [1206]
C182  100NF  DSC2: 10V  [1206]
C183  1uF  DSC2: 10V  [1206]
C184  1uF  DSC2: 10V  [1206]
C185  100NF  DSC2: 10V  [1206]
C186  NC/6.8pF  DSC2: 50V  [1206]
C187  4.7uF  DSC2: 10V  [1206]
C188  100NF  DSC2: 10V  [1206]
C189  100NF  DSC2: 10V  [1206]
C190  4.7uF  DSC2: 10V  [1206]
C191  100NF  DSC2: 10V  [1206]
C493  NC/6.8pF  DSC2: 50V  [1206]
C496  NC/6.8pF  DSC2: 50V  [1206]
D71  SRV05-4  [SOT23-6]
D72  SRV05-4  [SOT23-6]
J30  HR911130X  [HR911130X]
L32  2.2uH/2.1A  [L2520]
R183  2.2R  [R0402L]
R184  2.2R  [R0402L]
R185  2.2R  [R0402L]
R186  2.2R  [R0402L]
R187  2.2R  [R0402L]
R188  2.2R  [R0402L]
R189  2.2R  [R0402L]
R190  2.2R  [R0402L]
R191  510R  [R0402L]
R192  510R  [R0402L]
R193  100R  [R0402L]
R194  120R  [R0402L]
R195  NC/4.7K  [R0402L]
R196  4.7K  [R0402L]
R197  22R  [R0402L]
R198  22R  [R0402L]
R199  NC/4.7K  [R0402L]
R200  4.7K  [R0402L]
R201  22R  [R0402L]
R202  22R  [R0402L]
R203  4.7K  [R0402L]
R204  22R  [R0402L]
R205  22R  [R0402L]
R206  4.7K  [R0402L]
R207  4.7K  [R0402L]
R208  4.7K  [R0402L]
R209  NC/4.7K  [R0402L]
R210  4.7K  [R0402L]
R211  NC/4.7K  [R0402L]
R212  2.49K  [R0402L]
R213  4.7K  [R0402L]
R214  NC/4.7K  [R0402L]
R215  0R  [R0402L]
R216  NC/4.7K  [R0402L]
R217  4.7K  [R0402L]
R218  NC/10K  [R0402L]
R219  0R  [R0402L]
R220  1.8K  [R0402L]
R221  0R  [R0402L]
R222  NC/0R  [R0402L]
R223  22R  [R0402L]
R224  22R  [R0402L]
R225  22R  [R0402L]
R226  22R  [R0402L]
R227  22R  [R0402L]
R228  22R  [R0402L]
R229  0R  [R0402L]
U24  RTL8211F-CG  PCB Footprint: RTL8211F-CG-QFN40  [QFN40_5R00X5R00X0R80_T]
XT4  25MHz  [xtal_32x25_4p]

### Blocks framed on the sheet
Close to SOC: C174 C493 R197 R198 R201 R202 R204 R205
Close to PIN30: C175 C176 L32
Close to PIN21: C177
Close to PIN3,8,38: C178 C180 C181
Close to PIN28: C184 C185
Close to PHY: C186 C496 R223-R228
Close to PIN11,40: C188 C189
Close to PIN29: C190 C191

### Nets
GND: C169.1 C170.1 C171.1 C172.1 C173.1 C174.1 C175.1 C176.1 C177.1 C178.1 C179.1 C180.1 C181.1 C182.1 C183.1 C184.1 C185.1 C186.1 C187.1 C188.1 C189.1 C190.1 C191.1 C493.1 C496.1 D71.2 D72.2 J30.10(GND) R192.2 R194.2 R195.1 R199.1 R203.1 R206.1 R208.1 R210.1 R212.1 R213.1 R216.1 U24.41(E_Pad) XT4.2 XT4.4
GND_EARTH: J30.SH1 J30.SH2
VCC3V3_PHY0: C187.2 C188.2 C189.2 C190.2 C191.2 R191.2 R196.2 R200.2 R218.1 R229.2 U24.11(AVDD33) U24.29(DVDD33) U24.40(AVDD33)
VCC_1V8: R221.1
VCCIO_PHY0: C183.2 C184.2 C185.2 R220.2 R221.2 R222.2 U24.28(DVDD_RG)
VCCIO_PHY1: R207.2 R209.2 R211.2 R214.2 R217.2
VDD10_PHY0: C175.2 C176.2 C177.2 C178.2 C180.2 C181.2 L32.2 U24.3(AVDD10) U24.8(AVDD10) U24.21(DVDD10) U24.38(AVDD10)
VDD_3V3: R222.1 R229.1
GMAC0_INT/PMEB_GPIO3_B0: R215.2 ; off-sheet GMAC0_INT/PMEB_GPIO3_B0
GMAC0_MCLKINOUT: C171.2 R193.1 R194.1 ; off-sheet GMAC0_MCLKINOUT
GMAC0_MDC: U24.13(MDC) ; off-sheet GMAC0_MDC
GMAC0_MDIO: R220.1 U24.14(MDIO) ; off-sheet GMAC0_MDIO
GMAC0_RSTn_GPIO3_A5: R219.1 ; off-sheet GMAC0_RSTn_GPIO3_A5
GMAC0_RXCLK: C186.2 R227.2 ; off-sheet GMAC0_RXCLK
GMAC0_RXD0: R223.2 ; off-sheet GMAC0_RXD0
GMAC0_RXD1: R224.2 ; off-sheet GMAC0_RXD1
GMAC0_RXD2: R225.2 ; off-sheet GMAC0_RXD2
GMAC0_RXD3: R226.2 ; off-sheet GMAC0_RXD3
GMAC0_RXDV_CRS: R228.2 ; off-sheet GMAC0_RXDV_CRS
GMAC0_TXCLK: C493.2 R205.1 ; off-sheet GMAC0_TXCLK
GMAC0_TXCLK_: C174.2 R205.2 U24.20(TXC)
GMAC0_TXD0: R197.1 ; off-sheet GMAC0_TXD0
GMAC0_TXD0_: R197.2 U24.18(TXD0)
GMAC0_TXD1: R198.1 ; off-sheet GMAC0_TXD1
GMAC0_TXD1_: R198.2 U24.17(TXD1)
GMAC0_TXD2: R201.1 ; off-sheet GMAC0_TXD2
GMAC0_TXD2_: R201.2 U24.16(TXD2)
GMAC0_TXD3: R202.1 ; off-sheet GMAC0_TXD3
GMAC0_TXD3_: R202.2 U24.15(TXD3)
GMAC0_TXEN: R204.1 ; off-sheet GMAC0_TXEN
GMAC0_TXEN_: R204.2 U24.19(TXCTL)
LAN0_A+: D72.6 J30.2(MDI_0+) R190.2
LAN0_A-: D72.1 J30.3(MDI_0-) R189.2
LAN0_B+: D72.3 J30.4(MDI_1+) R188.2
LAN0_B-: D72.4 J30.7(MDI_1-) R187.2
LAN0_C+: D71.6 J30.5(MDI_2+) R186.2
LAN0_C-: D71.1 J30.6(MDI_2-) R185.2
LAN0_D+: D71.3 J30.8(MDI_3+) R184.2
LAN0_D-: D71.4 J30.9(MDI_3-) R183.2
PHY0_CLKOUT125: R193.2 U24.35(CLKOUT)
PHY0_G_LED-: J30.12(G_LED-) R192.1
PHY0_LED0/CFG_EXT: R195.2 R196.1 U24.32(LED0/CFG_EXT)
PHY0_LED1/CFG_LDO0: C173.2 J30.11(G_LED+) R203.2 U24.33(LED1/CFG_LDO0)
PHY0_LED2/CFG_LDO1: C172.2 J30.13(Y_LED-) R199.2 R200.1 U24.34(LED2/CFG_LDO1)
PHY0_MDI0+: R190.1 U24.1(MDI[0]+)
PHY0_MDI0-: R189.1 U24.2(MDI[0]-)
PHY0_MDI1+: R188.1 U24.4(MDI[1]+)
PHY0_MDI1-: R187.1 U24.5(MDI[1]-)
PHY0_MDI2+: R186.1 U24.6(MDI[2]+)
PHY0_MDI2-: R185.1 U24.7(MDI[2]-)
PHY0_MDI3+: R184.1 U24.9(MDI[3]+)
PHY0_MDI3-: R183.1 U24.10(MDI[3]-)
PHY0_REG_OUT: L32.1 U24.30(REG_OUT)
PHY0_RSTn: C182.2 R218.2 R219.2 U24.12(PHYRSTB)
PHY0_RXCLK/PHYAD1: C496.2 R208.2 R209.1 R227.1 U24.27(RXC/PHYAD1)
PHY0_RXD0/RXDLY: R210.2 R211.1 R223.1 U24.25(RXD0/RXDLY)
PHY0_RXD1/TXDLY: R213.2 R214.1 R224.1 U24.24(RXD1/TXDLY)
PHY0_RXD2/PLLOFF: R216.2 R217.1 R225.1 U24.23(RXD2/PLLOFF)
PHY0_RXD3/PHYAD0: R207.1 R226.1 U24.22(RXD3/PHYAD0)
PHY0_RXDV/PHYAD2: R206.2 R228.1 U24.26(RXCTL/PHYAD2)
PHY0_XTALIN: C169.2 U24.36(XTAL_IN) XT4.3
PHY0_XTALOUT: C170.2 U24.37(XTAL_OUT/EXT_CLK) XT4.1
PHY0_Y_LED+: J30.14(Y_LED+) R191.1
RSET0: R212.2 U24.39(RSET)
NetC179_2: C179.2 J30.1(CT1/2/3/4)
NetR215_1: R215.1 U24.31(INTB/PMEB)

Not connected (* = marked no-connect by the designer): D71 5*; D72 5*

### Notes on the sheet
- Giga PHY1
- RGMII Power Source
- External 3.3V
- CFG_EXT
- 1'b1
- CFG_LDO[1:0]
- 2'b00
- External 1.8V
- Internal 1.8V (default)
- 1'b0
- 2'b10
- (near R193) MAC <----- PHY
- 3.3Vpp
- Reserve for EMI.
- (near R203) VCC_PHY0_IO Voltage Config
- (near R206) PHY Address Config
- PHY Address
- 1 (default)
- PHYAD[2:0]
- 3'b001
- Pull-up for additional 2ns delay to RXC for data latching
- Pull-up for additional 2ns delay to TXC for data latching
- Pull-up to disable PLL @ ALDPS mode(Low power mode)
- RTL8211F-CG(SW Mode)
- RTL8211FI-CG(SW Mode)Industrial
- Note:
- (near R221) According to the actual
  choice of mounted
  Cannot be mounted
  at the same time
- PHYRSTB is 3.3V IO

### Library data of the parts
C169 C170 = C-0402_Dup1: Manufacture: 三星¦国巨¦村田; Part Name: 贴片电容; Part Number: C020102120027; PCB Footprint: C0402L; ID: 27; DSC3: C0G; DSC1: ±5%; ERP Number: 1010200091
C171 C186 = C-0402_Dup1: as C270 on sheet P16
C172 = C-0402_Dup1: Part Number: C020102120040; Part Name: 贴片电容; Manufacture: 三星¦国巨¦村田; PCB Footprint: C0402L; ERP Number: 1010200152; DSC1: ±5%; DSC3: C0G; ID: 40
C173 = C-0402_Dup1: Manufacture: 三星¦国巨¦村田; Part Name: 贴片电容; Part Number: C020102120040; PCB Footprint: C0402L; ID: 40; DSC3: C0G; DSC1: ±5%; ERP Number: 1010200152
C174 = C-0402_Dup1: as C168 on sheet P17
C175 = C-0402_Dup1: Part Number: C020102120067; Part Name: 贴片电容; Manufacture: 三星¦国巨¦村田; PCB Footprint: C0402L; DSC1: ±20%; DSC3: X5R; ID: 67
C176-C178 C180 C181 = C-0402_Dup1: as C163 on sheet P17
C179 = C-0402_Dup1: Manufacture: 三星¦国巨¦村田; Part Name: 贴片电容; Part Number: C020102120057; ID: 57; DSC3: X7R; DSC1: ±10%; ERP Number: 1010200077; PCB Footprint: C0402L
C182 C185 C188 C189 C191 = C-0402_Dup1: Part Number: C020102120060; Part Name: 贴片电容; Manufacture: 三星¦国巨¦村田; PCB Footprint: C0402L; DSC1: ±10%; DSC3: X7R; ID: 60
C183 C184 = C-0402_Dup1: as C162 on sheet P17
C187 C190 = C-0402_Dup1: as C167 on sheet P17
C493 C496 = C-0402_Dup1: Part Number: C020102120018; Part Name: 贴片电容; Manufacture: 三星¦国巨¦村田; ERP Number: 1010200056; DSC1: ±0.25PF; DSC3: C0G; ID: 18; PCB Footprint: C0402L
D71 = DI-ESD-SRV05-4: Manufacture: 伯恩半导体; Part Name: TVS; Part Number: C040602260015; Solder: 量产; ID: 15; DSC7: Cj=0.36pF; DSC6: Ppp=45W; DSC5: Ipp=3.5A; DSC4: Vc=13V; DSC3: VBR=6V; DSC2: Vrwm=5V; DSC1: 单向; ERP Number: 1010800050
D72 = DI-ESD-SRV05-4: Part Number: C040602260015; Part Name: TVS; Manufacture: 伯恩半导体; ERP Number: 1010800050; DSC1: 单向; DSC2: Vrwm=5V; DSC3: VBR=6V; DSC4: Vc=13V; DSC5: Ipp=3.5A; DSC6: Ppp=45W; DSC7: Cj=0.36pF; ID: 15; Solder: 量产
J30 = J-RJ45-HR911130C: Part Name: RJ45; Part Number: J120103060005; ID: 5; DSC4: HR911130C(汉仁); DSC3: 90度插件; DSC1: RJ45 内置千兆变压器带灯
L32 = L-IND_Dup1: Part Name: 功率电感; Part Number: C060202340014; Manufacture: 顺络; DSC1: ±20%; DSC2: Isat=2.3A; DSC3: Irms=2.1A; DSC4: 85mΩ; DSC5: 2.5*2.0*1.2mm; DSC6: WPN252012H2R2MTY01(顺络); ID: 14
R183-R190 = R-0402_Dup1: Part Number: C011002080453; Part Name: 贴片电阻; ID: 453; DSC2: 1/16W; DSC1: ±1%
R191 R192 = R-0402_Dup1: Part Name: 贴片电阻; Part Number: C011002080708; DSC1: ±1%; DSC2: 1/16W; ID: 708
R193 = R-0402_Dup1: Part Name: 贴片电阻; Part Number: C011002080630; ERP Number: 1010200450; DSC1: ±1%; DSC2: 1/16W; ID: 630
R194 = R-0402_Dup1: Part Number: C011002080638; Part Name: 贴片电阻; ID: 638; DSC2: 1/16W; DSC1: ±1%
R195 R199 R209 R211 R214 R216 = R-0402_Dup1: Part Name: 贴片电阻; Part Number: C011002080818; ERP Number: 1010200445; DSC1: ±1%; DSC2: 1/16W; ID: 818
R196 R200 R203 R206-R208 R210 R213 R217 = R-0402_Dup1: Part Number: C011002080818; Part Name: 贴片电阻; ID: 818; DSC2: 1/16W; DSC1: ±1%; ERP Number: 1010200445
R197 R198 R201 R202 R204 R205 R223-R228 = R-0402_Dup1: as R144 on sheet P16
R212 = R-0402_Dup1: Part Name: 贴片电阻; Part Number: C011002080785; ERP Number: 1010200324; DSC1: ±1%; DSC2: 1/16W; ID: 785
R215 R221 = R-0402_Dup1: as R142 on sheet P16
R218 = R-0402_Dup1: as R173 on sheet P17
R219 R222 R229 = R-0402_Dup1: as R132-R141 on sheet P16
R220 = R-0402_Dup1: Part Name: 贴片电阻; Part Number: C011002080769; DSC1: ±1%; DSC2: 1/16W; ID: 769
U24 = Ethernet_RTL8211F: Integrated 10/100/1000 Gigabit Ethernet Transceiver，Supports IEEE 802.3az-2010,; Manufacturer: RealTek(瑞昱); Priority: A
XT4 = XTAL-4P: Part Name: 贴片无源晶振; Part Number: C050102290006; Manufacture: 泰晶; CLASS: IC; DSC1: 40Ω; DSC2: ±10ppm; DSC3: 12pF; DSC4: -40℃~+85℃; DSC5: 3.2*2.5mm 4P; ID: 6

## Sheet P19.SchDoc
size 594 x 420 mm
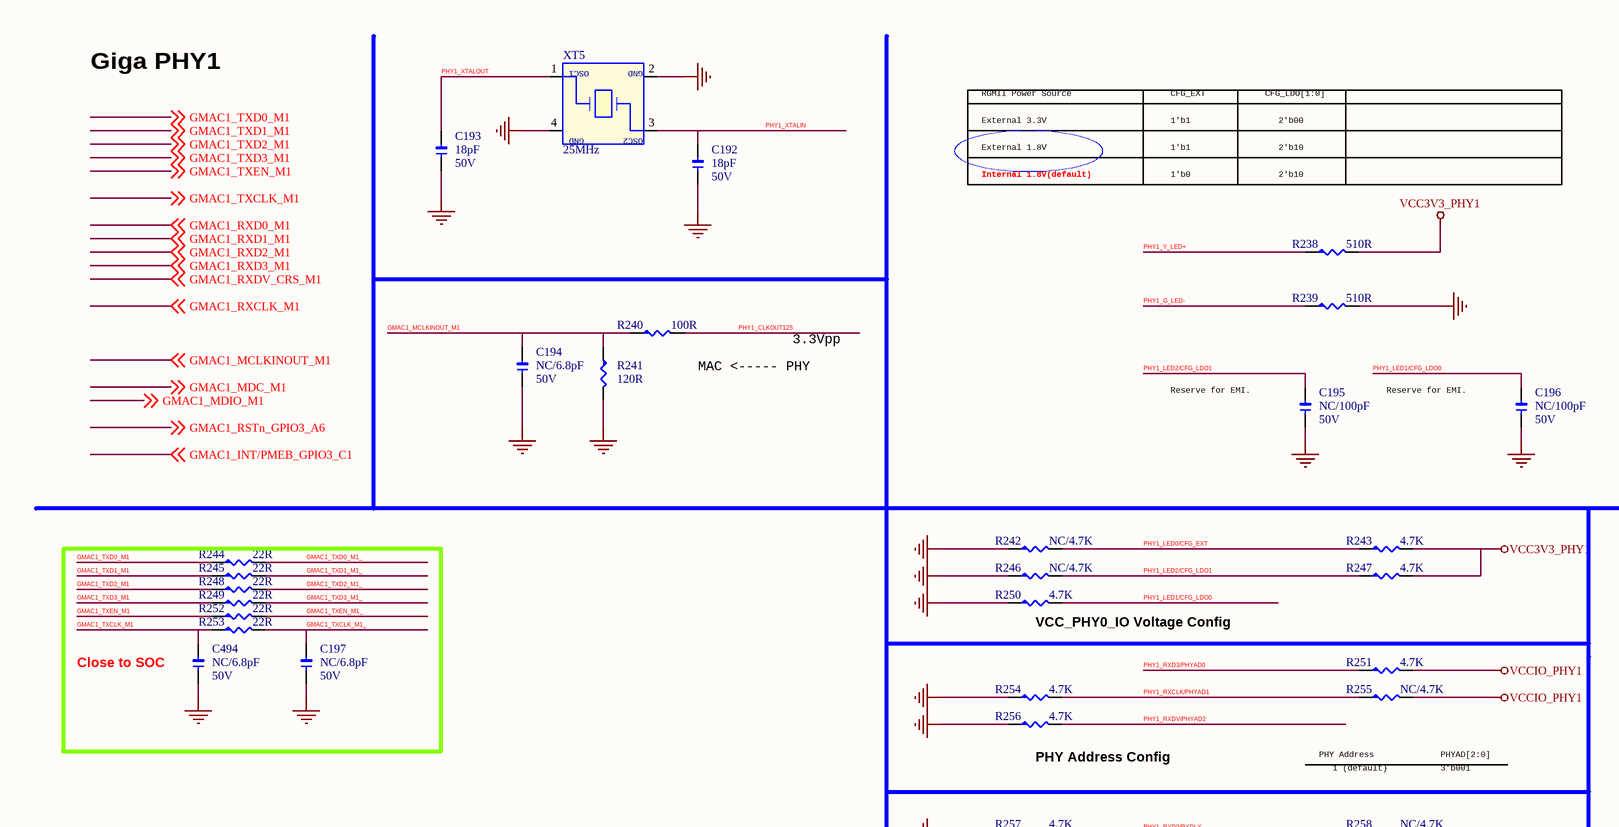
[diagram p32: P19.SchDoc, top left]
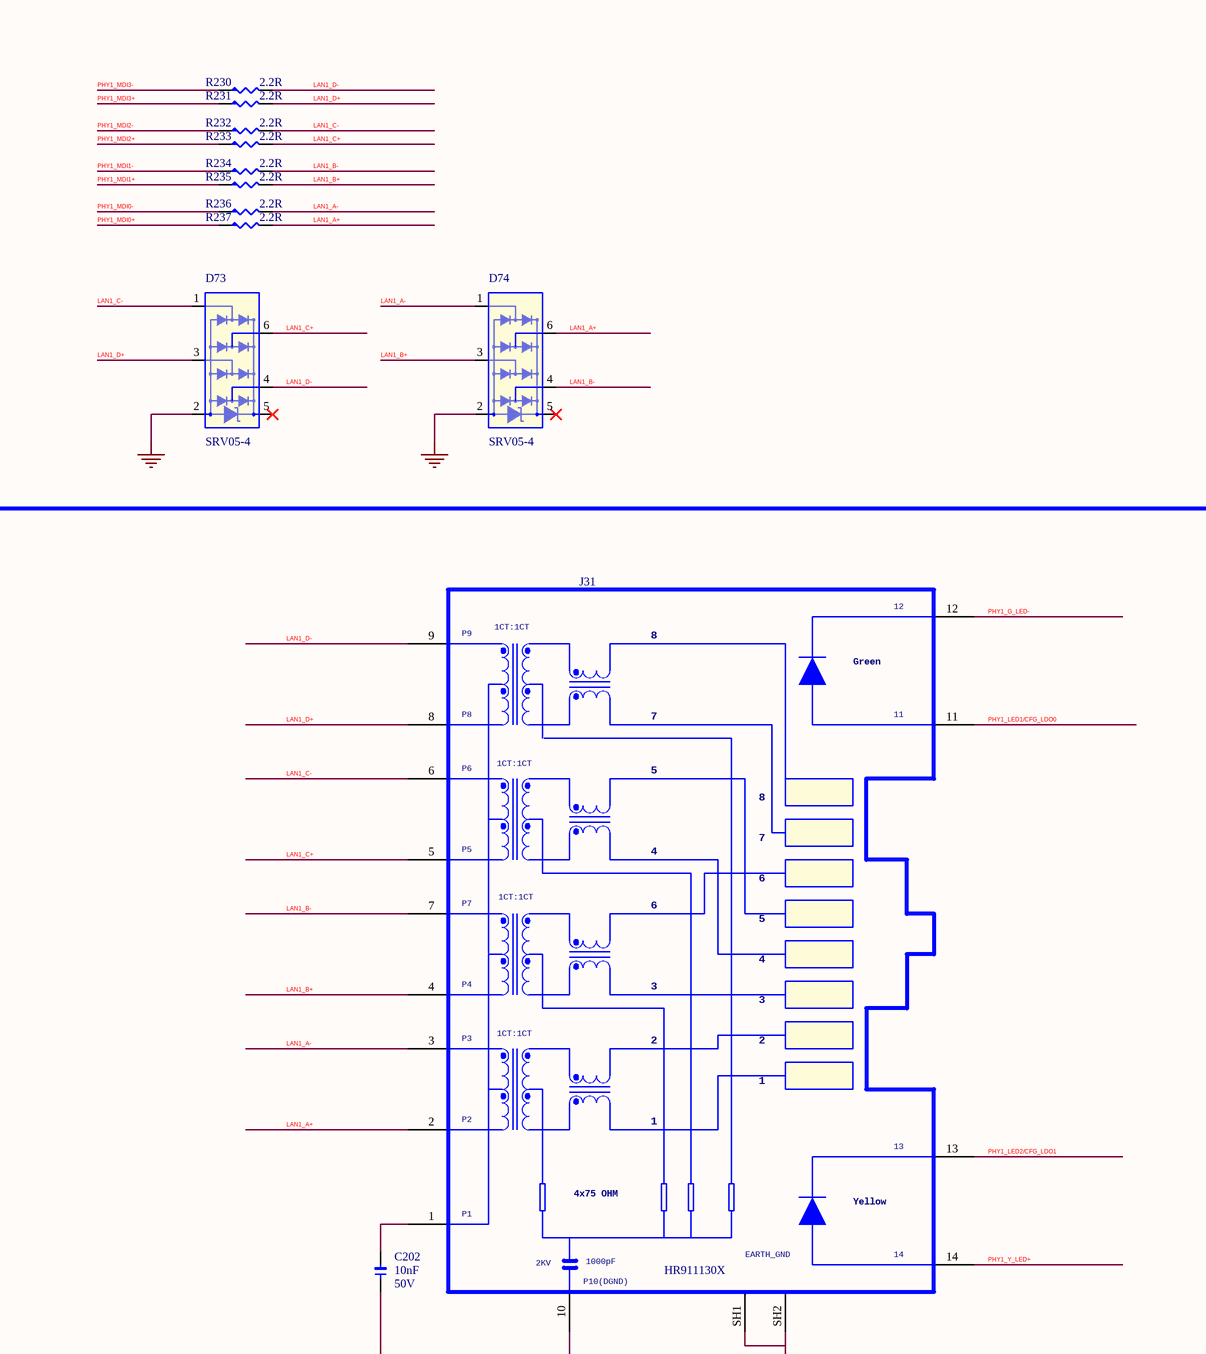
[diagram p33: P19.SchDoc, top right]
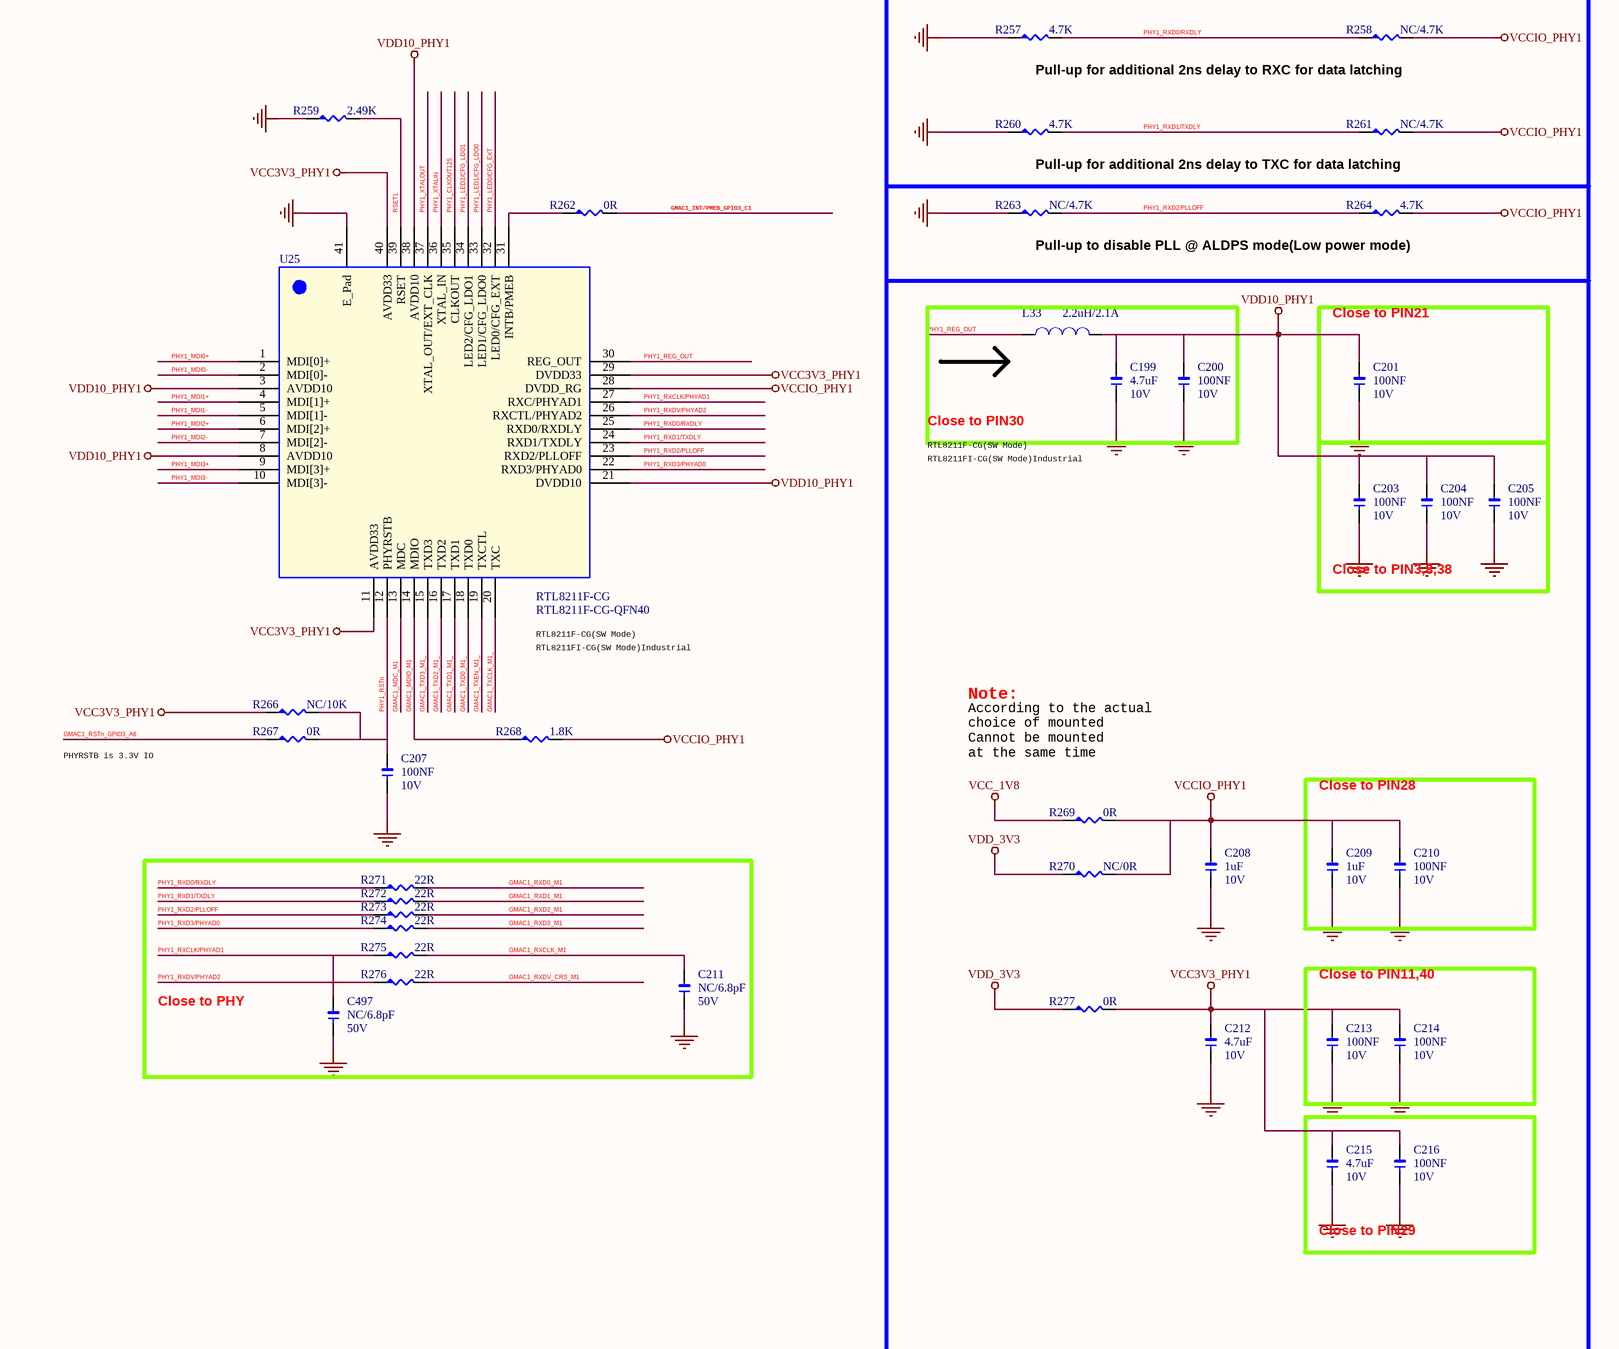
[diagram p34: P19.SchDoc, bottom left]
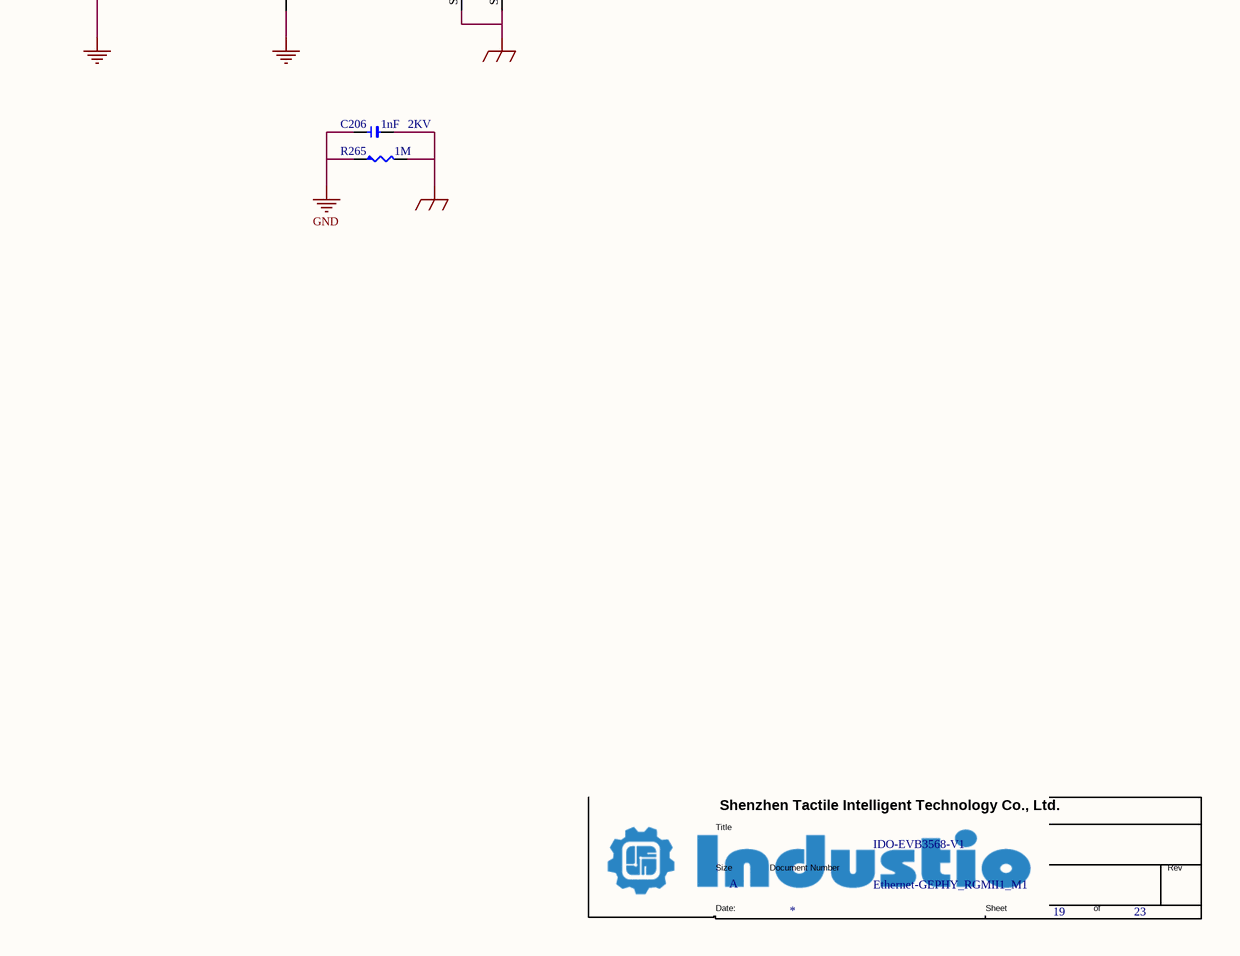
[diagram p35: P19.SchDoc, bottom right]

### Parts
(Parts that share a designator on the sheet are numbered #1, #2 ... from top to bottom, then left to right.)
*#19  Doc: Ethernet-GEPHY_RGMII1_M1  Title: IDO-EVB3568-V1  Page Size: A  Page Number: 19  Page Count: 23  (hidden comment: TitleBlock1)  (graphical)
C192  18pF  DSC2: 50V  [1206]
C193  18pF  DSC2: 50V  [1206]
C194  NC/6.8pF  DSC2: 50V  [1206]
C195  NC/100pF  DSC2: 50V  [1206]
C196  NC/100pF  DSC2: 50V  [1206]
C197  NC/6.8pF  DSC2: 50V  [1206]
C199  4.7uF  DSC2: 10V  [1206]
C200  100NF  DSC2: 10V  [1206]
C201  100NF  DSC2: 10V  [1206]
C202  10nF  DSC2: 50V  [1206]
C203  100NF  DSC2: 10V  [1206]
C204  100NF  DSC2: 10V  [1206]
C205  100NF  DSC2: 10V  [1206]
C206  1nF  DSC2: 2KV  [1206]
C207  100NF  DSC2: 10V  [1206]
C208  1uF  DSC2: 10V  [1206]
C209  1uF  DSC2: 10V  [1206]
C210  100NF  DSC2: 10V  [1206]
C211  NC/6.8pF  DSC2: 50V  [1206]
C212  4.7uF  DSC2: 10V  [1206]
C213  100NF  DSC2: 10V  [1206]
C214  100NF  DSC2: 10V  [1206]
C215  4.7uF  DSC2: 10V  [1206]
C216  100NF  DSC2: 10V  [1206]
C494  NC/6.8pF  DSC2: 50V  [1206]
C497  NC/6.8pF  DSC2: 50V  [1206]
D73  SRV05-4  [SOT23-6]
D74  SRV05-4  [SOT23-6]
J31  HR911130X  [HR911130X]
L33  2.2uH/2.1A  [L2520]
R230  2.2R  [R0402L]
R231  2.2R  [R0402L]
R232  2.2R  [R0402L]
R233  2.2R  [R0402L]
R234  2.2R  [R0402L]
R235  2.2R  [R0402L]
R236  2.2R  [R0402L]
R237  2.2R  [R0402L]
R238  510R  [R0402L]
R239  510R  [R0402L]
R240  100R  [R0402L]
R241  120R  [R0402L]
R242  NC/4.7K  [R0402L]
R243  4.7K  [R0402L]
R244  22R  [R0402L]
R245  22R  [R0402L]
R246  NC/4.7K  [R0402L]
R247  4.7K  [R0402L]
R248  22R  [R0402L]
R249  22R  [R0402L]
R250  4.7K  [R0402L]
R251  4.7K  [R0402L]
R252  22R  [R0402L]
R253  22R  [R0402L]
R254  4.7K  [R0402L]
R255  NC/4.7K  [R0402L]
R256  4.7K  [R0402L]
R257  4.7K  [R0402L]
R258  NC/4.7K  [R0402L]
R259  2.49K  [R0402L]
R260  4.7K  [R0402L]
R261  NC/4.7K  [R0402L]
R262  0R  [R0402L]
R263  NC/4.7K  [R0402L]
R264  4.7K  [R0402L]
R265  1M  [R0805L]
R266  NC/10K  [R0402L]
R267  0R  [R0402L]
R268  1.8K  [R0402L]
R269  0R  [R0402L]
R270  NC/0R  [R0402L]
R271  22R  [R0402L]
R272  22R  [R0402L]
R273  22R  [R0402L]
R274  22R  [R0402L]
R275  22R  [R0402L]
R276  22R  [R0402L]
R277  0R  [R0402L]
U25  RTL8211F-CG  PCB Footprint: RTL8211F-CG-QFN40  [QFN40_5R00X5R00X0R80_T]
XT5  25MHz  [xtal_32x25_4p]

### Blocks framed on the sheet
Close to SOC: C197 C494 R244 R245 R248 R249 R252 R253
Close to PIN30: C199 C200 L33
Close to PIN21: C201
Close to PIN3,8,38: C203-C205
Close to PIN28: C209 C210
Close to PHY: C211 C497 R271-R276
Close to PIN11,40: C213 C214
Close to PIN29: C215 C216

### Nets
GND: C192.1 C193.1 C194.1 C195.1 C196.1 C197.1 C199.1 C200.1 C201.1 C202.1 C203.1 C204.1 C205.1 C206.1 C207.1 C208.1 C209.1 C210.1 C211.1 C212.1 C213.1 C214.1 C215.1 C216.1 C494.1 C497.1 D73.2 D74.2 J31.10(GND) R239.2 R241.2 R242.1 R246.1 R250.1 R254.1 R256.1 R257.1 R259.1 R260.1 R263.1 R265.1 U25.41(E_Pad) XT5.2 XT5.4
GND_EARTH: C206.2 J31.SH1 J31.SH2 R265.2
VCC3V3_PHY1: C212.2 C213.2 C214.2 C215.2 C216.2 R238.2 R243.2 R247.2 R266.1 R277.2 U25.11(AVDD33) U25.29(DVDD33) U25.40(AVDD33)
VCC_1V8: R269.1
VCCIO_PHY1: C208.2 C209.2 C210.2 R251.2 R255.2 R258.2 R261.2 R264.2 R268.2 R269.2 R270.2 U25.28(DVDD_RG)
VDD10_PHY1: C199.2 C200.2 C201.2 C203.2 C204.2 C205.2 L33.2 U25.3(AVDD10) U25.8(AVDD10) U25.21(DVDD10) U25.38(AVDD10)
VDD_3V3: R270.1 R277.1
GMAC1_INT/PMEB_GPIO3_C1: R262.2 ; off-sheet GMAC1_INT/PMEB_GPIO3_C1
GMAC1_MCLKINOUT_M1: C194.2 R240.1 R241.1 ; off-sheet GMAC1_MCLKINOUT_M1  [project net CIF_CLKIN/EBC_SDCLK/GMAC1_MCLKINOUT_M1/UART1_CTSn_M1/I2S2_SCLK_RX_M1/GPIO4_C1_d]
GMAC1_MDC_M1: U25.13(MDC) ; off-sheet GMAC1_MDC_M1  [project net CIF_HREF/EBC_SDLE/GMAC1_MDC_M1/UART1_RTSn_M1/I2S2_MCLK_M1/GPIO4_B6_d]
GMAC1_MDIO_M1: R268.1 U25.14(MDIO) ; off-sheet GMAC1_MDIO_M1  [project net CIF_VSYNC/EBC_SDOE/GMAC1_MDIO_M1/I2S2_SCLK_TX_M1/GPIO4_B7_d]
GMAC1_RSTn_GPIO3_A6: R267.1 ; off-sheet GMAC1_RSTn_GPIO3_A6
GMAC1_RXCLK_M1: C211.2 R275.2 ; off-sheet GMAC1_RXCLK_M1  [project net CIF_D13/EBC_SDDO13/GMAC1_RXCLK_M1/UART7_RX_M2/PDM_SDI3_M1/GPIO4_A3_d]
GMAC1_RXD0_M1: R271.2 ; off-sheet GMAC1_RXD0_M1  [project net CAM_CLKOUT0/EBC_SDCE1/GMAC1_RXD0_M1/SPI3_CS1_M0/I2S1_LRCK_RX_M1/GPIO4_A7_d]
GMAC1_RXD1_M1: R272.2 ; off-sheet GMAC1_RXD1_M1  [project net CAM_CLKOUT1/EBC_SDCE2/GMAC1_RXD1_M1/SPI3_MISO_M0/I2S1_SDO1_M1/GPIO4_B0_d]
GMAC1_RXD2_M1: R273.2 ; off-sheet GMAC1_RXD2_M1  [project net CIF_D11/EBC_SDDO11/GMAC1_RXD2_M1/PDM_SDI1_M1/GPIO4_A1_d]
GMAC1_RXD3_M1: R274.2 ; off-sheet GMAC1_RXD3_M1  [project net CIF_D12/EBC_SDDO12/GMAC1_RXD3_M1/UART7_TX_M2/PDM_SDI2_M1/GPIO4_A2_d]
GMAC1_RXDV_CRS_M1: R276.2 ; off-sheet GMAC1_RXDV_CRS_M1
GMAC1_TXCLK_M1: C494.2 R253.1 ; off-sheet GMAC1_TXCLK_M1  [project net CIF_D10/EBC_SDDO10/GMAC1_TXCLK_M1/PDM_CLK1_M1/GPIO4_A0_d]
GMAC1_TXCLK_M1_: C197.2 R253.2 U25.20(TXC)
GMAC1_TXD0_M1: R244.1 ; off-sheet GMAC1_TXD0_M1  [project net CIF_D14/EBC_SDDO14/GMAC1_TXD0_M1/UART9_TX_M2/I2S2_LRCK_TX_M1/GPIO4_A4_d]
GMAC1_TXD0_M1_: R244.2 U25.18(TXD0)
GMAC1_TXD1_M1: R245.1 ; off-sheet GMAC1_TXD1_M1  [project net CIF_D15/EBC_SDDO15/GMAC1_TXD1_M1/UART9_RX_M2/I2S2_LRCK_RX_M1/GPIO4_A5_d]
GMAC1_TXD1_M1_: R245.2 U25.17(TXD1)
GMAC1_TXD2_M1: R248.1 ; off-sheet GMAC1_TXD2_M1  [project net CIF_D8/EBC_SDDO8/GMAC1_TXD2_M1/UART1_TX_M1/PDM_CLK0_M1/GPIO3_D6_d]
GMAC1_TXD2_M1_: R248.2 U25.16(TXD2)
GMAC1_TXD3_M1: R249.1 ; off-sheet GMAC1_TXD3_M1  [project net CIF_D9/EBC_SDDO9/GMAC1_TXD3_M1/UART1_RX_M1/PDM_SDI0_M1/GPIO3_D7_d]
GMAC1_TXD3_M1_: R249.2 U25.15(TXD3)
GMAC1_TXEN_M1: R252.1 ; off-sheet GMAC1_TXEN_M1
GMAC1_TXEN_M1_: R252.2 U25.19(TXCTL)
LAN1_A+: D74.6 J31.2(MDI_0+) R237.2
LAN1_A-: D74.1 J31.3(MDI_0-) R236.2
LAN1_B+: D74.3 J31.4(MDI_1+) R235.2
LAN1_B-: D74.4 J31.7(MDI_1-) R234.2
LAN1_C+: D73.6 J31.5(MDI_2+) R233.2
LAN1_C-: D73.1 J31.6(MDI_2-) R232.2
LAN1_D+: D73.3 J31.8(MDI_3+) R231.2
LAN1_D-: D73.4 J31.9(MDI_3-) R230.2
PHY1_CLKOUT125: R240.2 U25.35(CLKOUT)
PHY1_G_LED-: J31.12(G_LED-) R239.1
PHY1_LED0/CFG_EXT: R242.2 R243.1 U25.32(LED0/CFG_EXT)
PHY1_LED1/CFG_LDO0: C196.2 J31.11(G_LED+) R250.2 U25.33(LED1/CFG_LDO0)
PHY1_LED2/CFG_LDO1: C195.2 J31.13(Y_LED-) R246.2 R247.1 U25.34(LED2/CFG_LDO1)
PHY1_MDI0+: R237.1 U25.1(MDI[0]+)
PHY1_MDI0-: R236.1 U25.2(MDI[0]-)
PHY1_MDI1+: R235.1 U25.4(MDI[1]+)
PHY1_MDI1-: R234.1 U25.5(MDI[1]-)
PHY1_MDI2+: R233.1 U25.6(MDI[2]+)
PHY1_MDI2-: R232.1 U25.7(MDI[2]-)
PHY1_MDI3+: R231.1 U25.9(MDI[3]+)
PHY1_MDI3-: R230.1 U25.10(MDI[3]-)
PHY1_REG_OUT: L33.1 U25.30(REG_OUT)
PHY1_RSTn: C207.2 R266.2 R267.2 U25.12(PHYRSTB)
PHY1_RXCLK/PHYAD1: C497.2 R254.2 R255.1 R275.1 U25.27(RXC/PHYAD1)
PHY1_RXD0/RXDLY: R257.2 R258.1 R271.1 U25.25(RXD0/RXDLY)
PHY1_RXD1/TXDLY: R260.2 R261.1 R272.1 U25.24(RXD1/TXDLY)
PHY1_RXD2/PLLOFF: R263.2 R264.1 R273.1 U25.23(RXD2/PLLOFF)
PHY1_RXD3/PHYAD0: R251.1 R274.1 U25.22(RXD3/PHYAD0)
PHY1_RXDV/PHYAD2: R256.2 R276.1 U25.26(RXCTL/PHYAD2)
PHY1_XTALIN: C192.2 U25.36(XTAL_IN) XT5.3
PHY1_XTALOUT: C193.2 U25.37(XTAL_OUT/EXT_CLK) XT5.1
PHY1_Y_LED+: J31.14(Y_LED+) R238.1
RSET1: R259.2 U25.39(RSET)
NetC202_2: C202.2 J31.1(CT1/2/3/4)
NetR262_1: R262.1 U25.31(INTB/PMEB)

Not connected (* = marked no-connect by the designer): D73 5*; D74 5*

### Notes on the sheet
- Giga PHY1
- RGMII Power Source
- CFG_EXT
- CFG_LDO[1:0]
- External 3.3V
- External 1.8V
- Internal 1.8V(default)
- 1'b1
- 1'b0
- 2'b00
- 2'b10
- (near R240) MAC <----- PHY
- 3.3Vpp
- Reserve for EMI.
- (near R250) VCC_PHY0_IO Voltage Config
- (near R256) PHY Address Config
- PHY Address
- 1 (default)
- PHYAD[2:0]
- 3'b001
- Pull-up for additional 2ns delay to RXC for data latching
- Pull-up for additional 2ns delay to TXC for data latching
- Pull-up to disable PLL @ ALDPS mode(Low power mode)
- RTL8211F-CG(SW Mode)
- RTL8211FI-CG(SW Mode)Industrial
- Note:
- (near R269) According to the actual
  choice of mounted
  Cannot be mounted
  at the same time
- PHYRSTB is 3.3V IO

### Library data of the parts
C192 C193 = C-0402_Dup1: as C158 on sheet P17
C194 C211 = C-0402_Dup1: Manufacture: 三星¦国巨¦村田; Part Name: 贴片电容; Part Number: C020102120018; ID: 18; DSC3: C0G; DSC1: ±0.25PF; ERP Number: 1010200056; PCB Footprint: C0402L
C195 = C-0402_Dup1: as C172 on sheet P18
C196 = C-0402_Dup1: as C173 on sheet P18
C197 C494 C497 = C-0402_Dup1: as C493 on sheet P18
C199 = C-0402_Dup1: Part Number: C020102120067; Part Name: 贴片电容; Manufacture: 三星¦国巨¦村田; DSC1: ±20%; DSC3: X5R; ID: 67; PCB Footprint: C0402L
C200 C201 C203-C205 = C-0402_Dup1: as C149 on sheet P16
C202 = C-0402_Dup1: Part Number: C020102120057; Part Name: 贴片电容; Manufacture: 三星¦国巨¦村田; ERP Number: 1010200077; DSC1: ±10%; DSC3: X7R; ID: 57; PCB Footprint: C0402L
C206 = C-1206: Part Number: C020102120077; Part Name: 贴片电容; Manufacture: 三星¦国巨¦村田; ERP Number: 1010200094; DSC1: ±10%; DSC3: X7R; ID: 77; PCB Footprint: C1206L
C207 C210 C213 C214 C216 = C-0402_Dup1: as C145 on sheet P16
C208 C209 = C-0402_Dup1: Manufacture: 三星¦国巨¦村田; Part Name: 贴片电容; Part Number: C020102120064; ID: 64; DSC3: X5R; DSC1: ±10%; ERP Number: 1010200054; PCB Footprint: C0402L
C212 C215 = C-0402_Dup1: Manufacture: 三星¦国巨¦村田; Part Name: 贴片电容; Part Number: C020102120067; ID: 67; DSC3: X5R; DSC1: ±20%; PCB Footprint: C0402L
D73 = DI-ESD-SRV05-4: as D71 on sheet P18
D74 = DI-ESD-SRV05-4: as D72 on sheet P18
J31 = J-RJ45-HR911130C: Part Number: J120103060005; Part Name: RJ45; DSC1: RJ45 内置千兆变压器带灯; DSC3: 90度插件; DSC4: HR911130C(汉仁); ID: 5
L33 = L-IND_Dup1: as L32 on sheet P18
R230-R237 = R-0402_Dup1: as R183 on sheet P18
R238 R239 = R-0402_Dup1: as R191 on sheet P18
R240 = R-0402_Dup1: as R193 on sheet P18
R241 = R-0402_Dup1: as R194 on sheet P18
R242 R246 R255 R258 R261 R263 = R-0402_Dup1: as R195 on sheet P18
R243 R247 R250 R251 R254 R256 R257 R260 R264 = R-0402_Dup1: as R196 on sheet P18
R244 R245 R248 R249 R252 R253 R271-R276 = R-0402_Dup1: as R144 on sheet P16
R259 = R-0402_Dup1: as R212 on sheet P18
R262 R269 = R-0402_Dup1: as R142 on sheet P16
R265 = R-0805: Part Name: 贴片电阻; Part Number: C011002081864; ERP Number: 1010200447; DSC1: ±1%; DSC2: 1/8W; ID: 1,864
R266 = R-0402_Dup1: as R148-R151 on sheet P16
R267 R270 R277 = R-0402_Dup1: as R132-R141 on sheet P16
R268 = R-0402_Dup1: as R220 on sheet P18
U25 = Ethernet_RTL8211F: as U24 on sheet P18
XT5 = XTAL-4P: as XT4 on sheet P18

## Sheet P20.SchDoc
size 594 x 420 mm
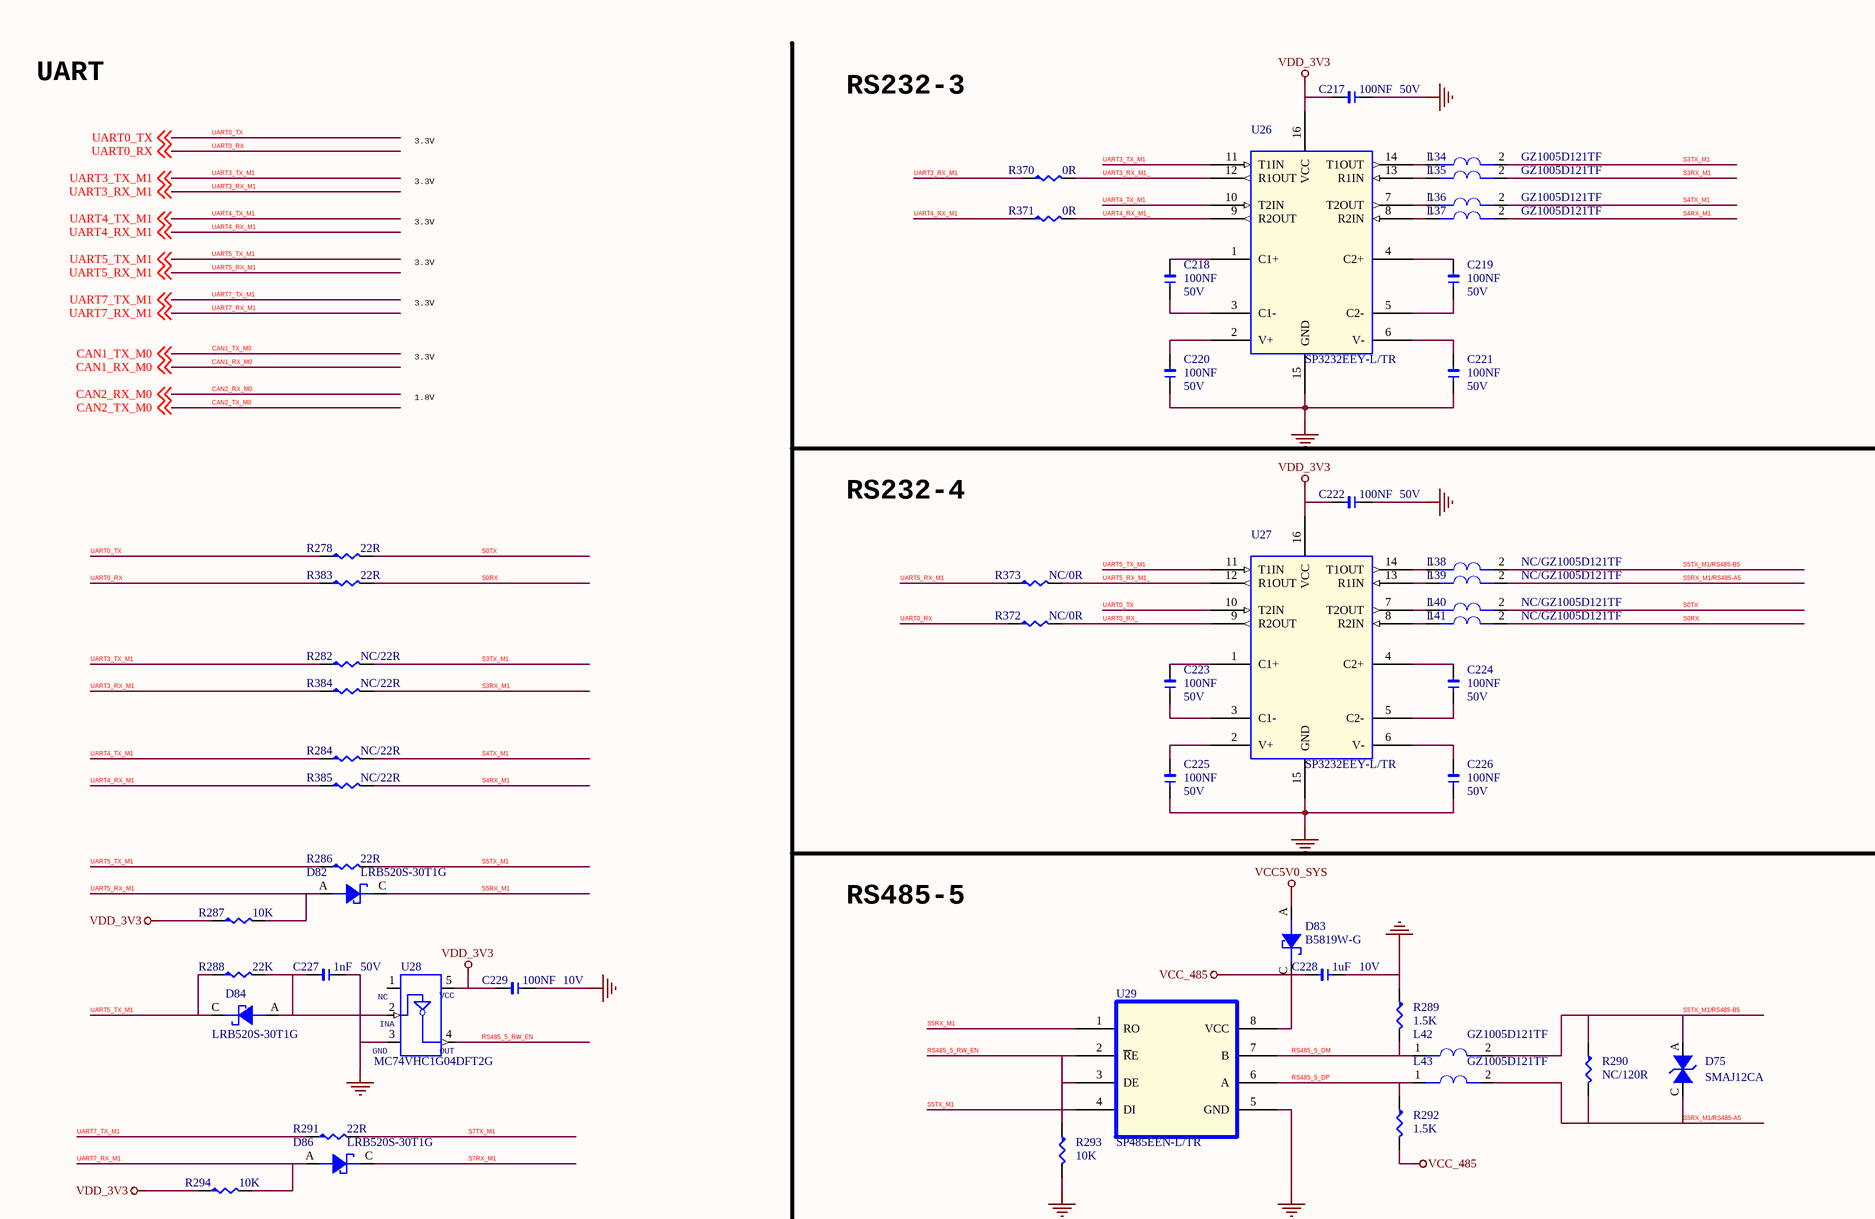
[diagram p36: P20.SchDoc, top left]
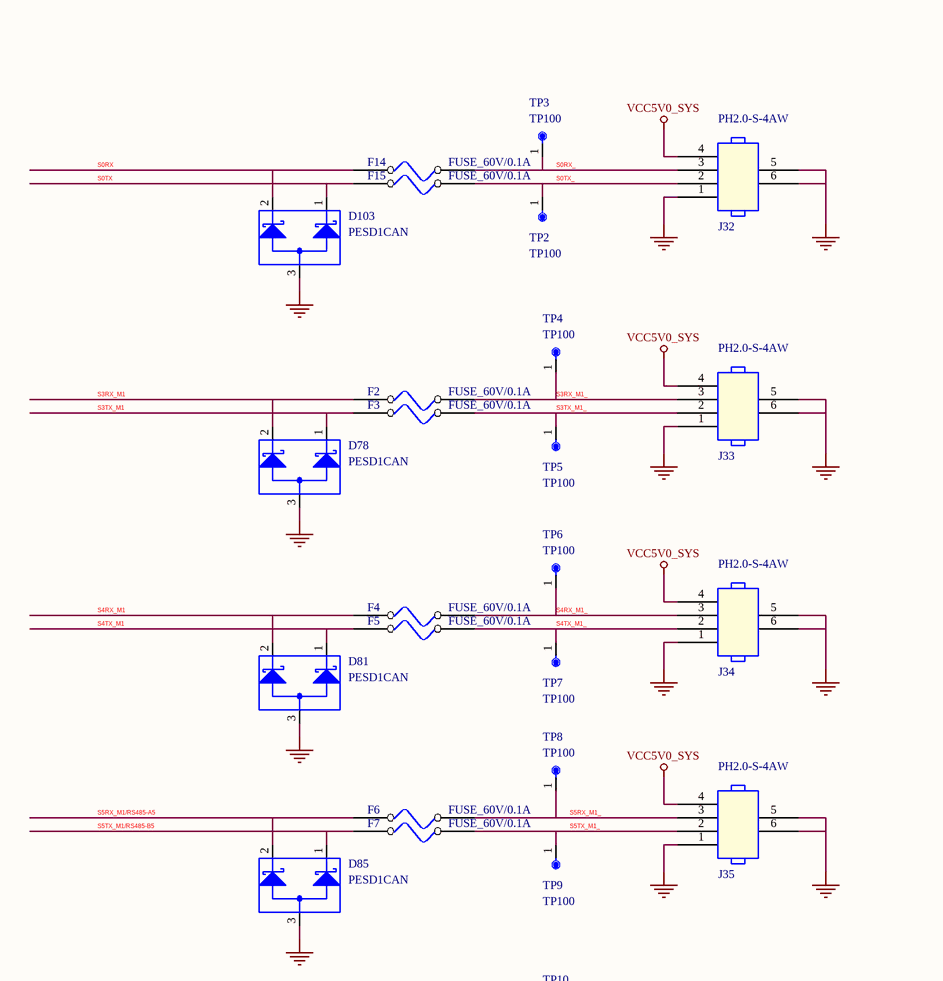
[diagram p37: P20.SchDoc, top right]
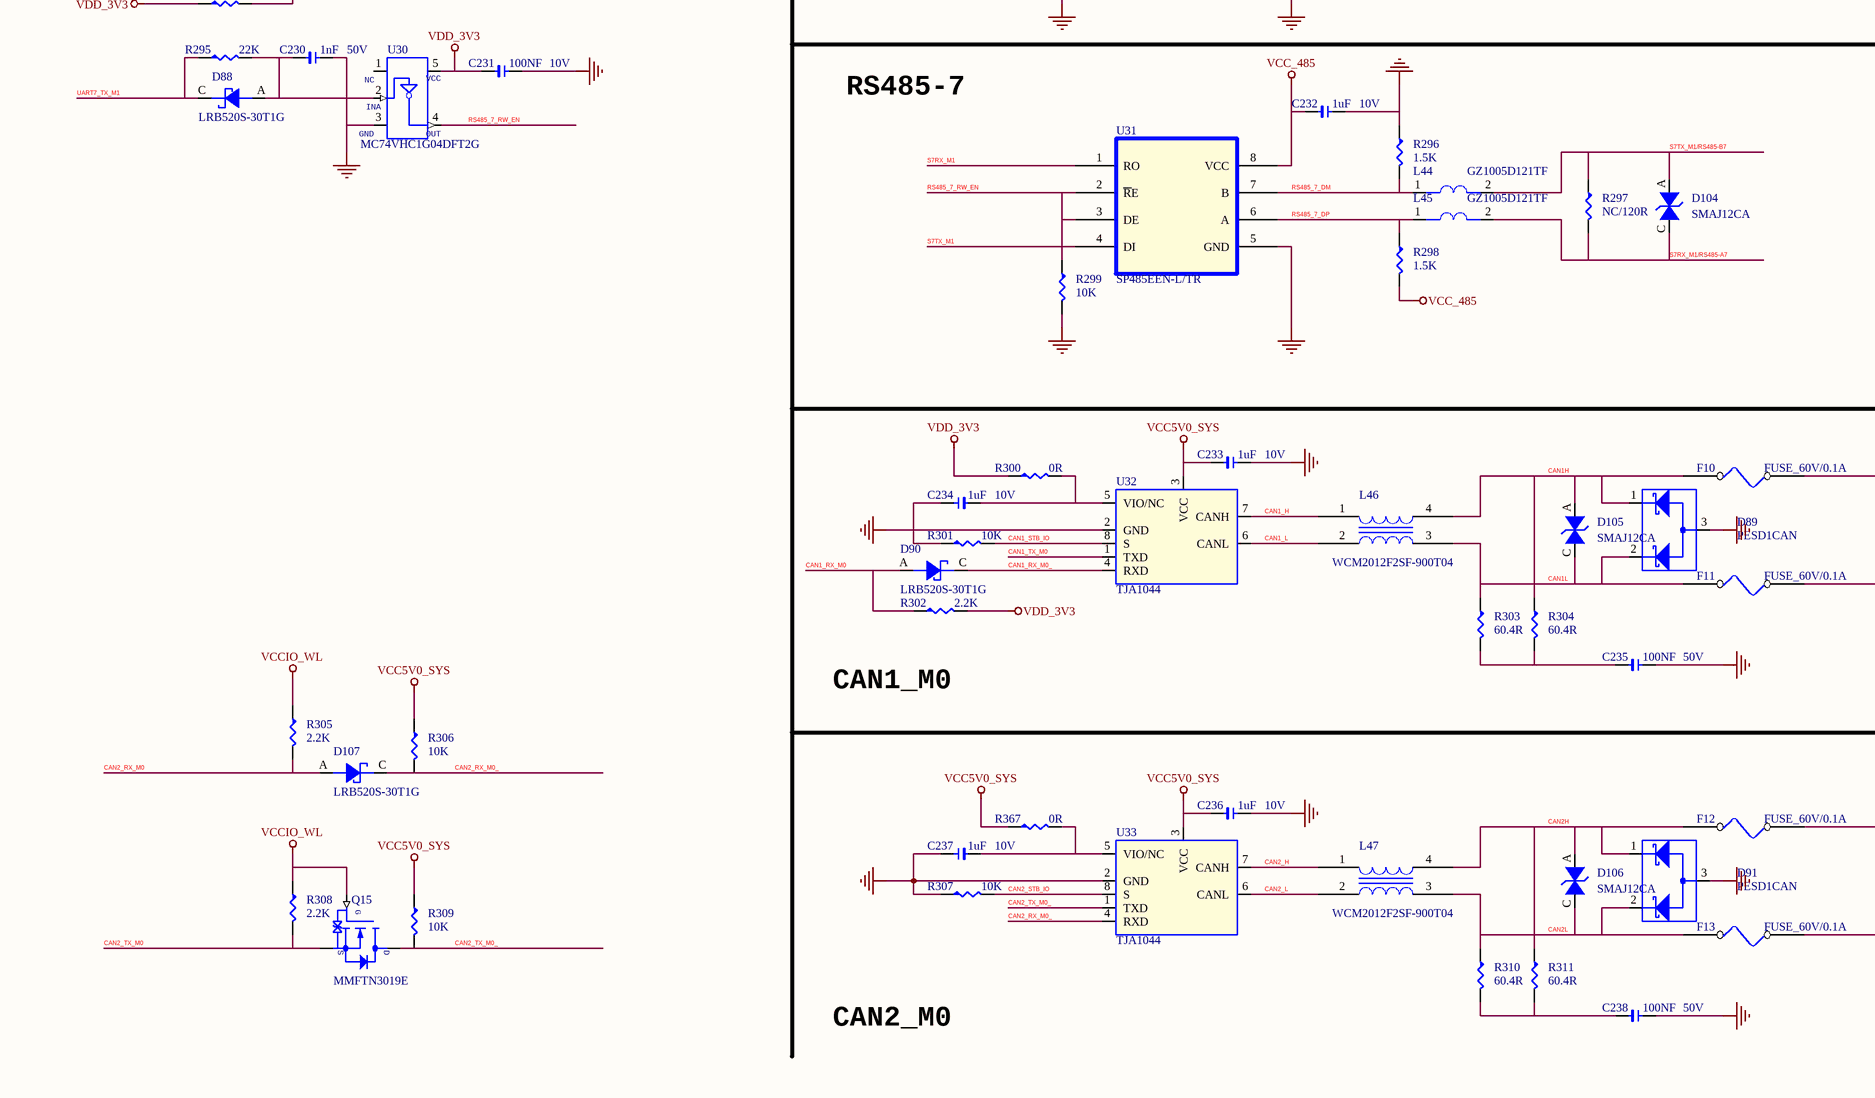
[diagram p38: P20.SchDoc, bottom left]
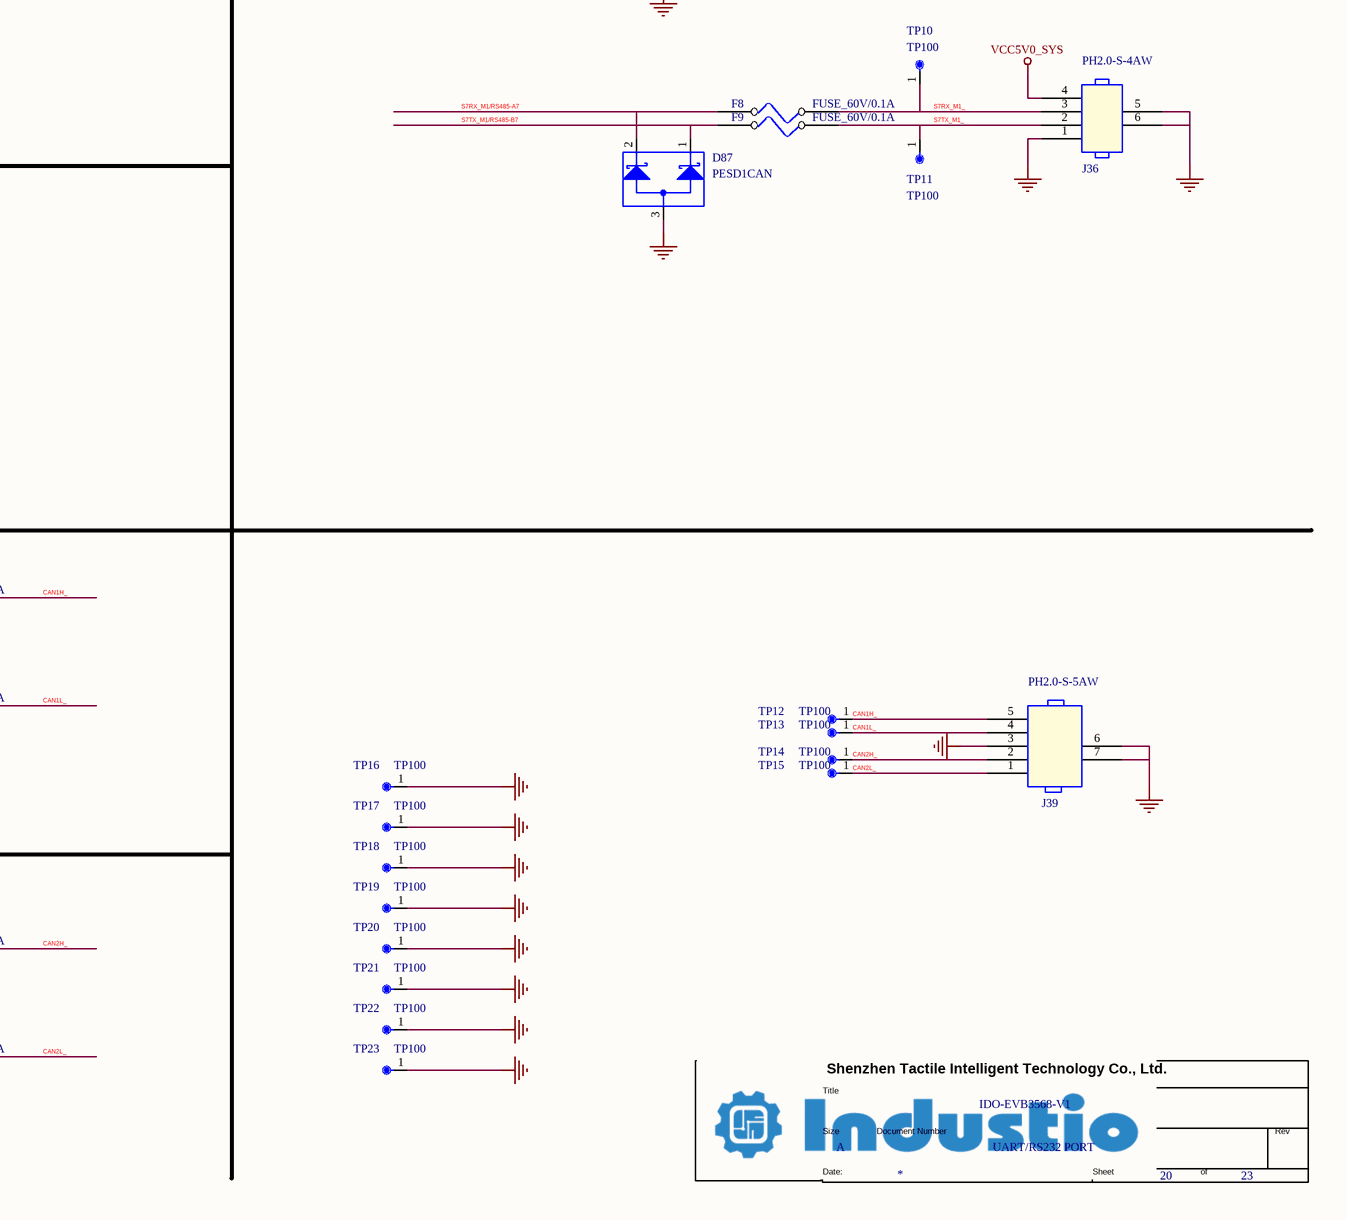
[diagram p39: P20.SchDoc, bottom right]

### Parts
(Parts that share a designator on the sheet are numbered #1, #2 ... from top to bottom, then left to right.)
*#20  Doc: UART/RS232 PORT  Title: IDO-EVB3568-V1  Page Size: A  Page Number: 20  Page Count: 23  (hidden comment: TitleBlock1)  (graphical)
C217  100NF  DSC2: 50V  [1206]
C218  100NF  DSC2: 50V  [1206]
C219  100NF  DSC2: 50V  [1206]
C220  100NF  DSC2: 50V  [1206]
C221  100NF  DSC2: 50V  [1206]
C222  100NF  DSC2: 50V  [1206]
C223  100NF  DSC2: 50V  [1206]
C224  100NF  DSC2: 50V  [1206]
C225  100NF  DSC2: 50V  [1206]
C226  100NF  DSC2: 50V  [1206]
C227  1nF  DSC2: 50V  [1206]
C228  1uF  DSC2: 10V  [1206]
C229  100NF  DSC2: 10V  [1206]
C230  1nF  DSC2: 50V  [1206]
C231  100NF  DSC2: 10V  [1206]
C232  1uF  DSC2: 10V  [1206]
C233  1uF  DSC2: 10V  [1206]
C234  1uF  DSC2: 10V  [1206]
C235  100NF  DSC2: 50V  [1206]
C236  1uF  DSC2: 10V  [1206]
C237  1uF  DSC2: 10V  [1206]
C238  100NF  DSC2: 50V  [1206]
D75  SMAJ12CA  [SMA_DO-214AC]
D78  PESD1CAN  [SOT23]
D81  PESD1CAN  [SOT23]
D82  LRB520S-30T1G  [SOD523]
D83  B5819W-G  [SOD123]
D84  LRB520S-30T1G  [SOD523]
D85  PESD1CAN  [SOT23]
D86  LRB520S-30T1G  [SOD523]
D87  PESD1CAN  [SOT23]
D88  LRB520S-30T1G  [SOD523]
D89  PESD1CAN  [SOT23]
D90  LRB520S-30T1G  [SOD523]
D91  PESD1CAN  [SOT23]
D103  PESD1CAN  [SOT23]
D104  SMAJ12CA  [SMA_DO-214AC]
D105  SMAJ12CA  [SMA_DO-214AC]
D106  SMAJ12CA  [SMA_DO-214AC]
D107  LRB520S-30T1G  [SOD523]
F2  FUSE_60V/0.1A  [SMD1206]
F3  FUSE_60V/0.1A  [SMD1206]
F4  FUSE_60V/0.1A  [SMD1206]
F5  FUSE_60V/0.1A  [SMD1206]
F6  FUSE_60V/0.1A  [SMD1206]
F7  FUSE_60V/0.1A  [SMD1206]
F8  FUSE_60V/0.1A  [SMD1206]
F9  FUSE_60V/0.1A  [SMD1206]
F10  FUSE_60V/0.1A  [SMD1206]
F11  FUSE_60V/0.1A  [SMD1206]
F12  FUSE_60V/0.1A  [SMD1206]
F13  FUSE_60V/0.1A  [SMD1206]
F14  FUSE_60V/0.1A  [SMD1206]
F15  FUSE_60V/0.1A  [SMD1206]
J32  PH2.0-S-4AW  [PH200-S-4AWZ]
J33  PH2.0-S-4AW  [PH200-S-4AWZ]
J34  PH2.0-S-4AW  [PH200-S-4AWZ]
J35  PH2.0-S-4AW  [PH200-S-4AWZ]
J36  PH2.0-S-4AW  [PH200-S-4AWZ]
J39  PH2.0-S-5AW  [PH200-S-5AWZ]
L34  GZ1005D121TF  [L0402]
L35  GZ1005D121TF  [L0402]
L36  GZ1005D121TF  [L0402]
L37  GZ1005D121TF  [L0402]
L38  NC/GZ1005D121TF  [L0402]
L39  NC/GZ1005D121TF  [L0402]
L40  NC/GZ1005D121TF  [L0402]
L41  NC/GZ1005D121TF  [L0402]
L42  GZ1005D121TF  [L0402]
L43  GZ1005D121TF  [L0402]
L44  GZ1005D121TF  [L0402]
L45  GZ1005D121TF  [L0402]
L46  WCM2012F2SF-900T04  [CMLS-ACM2012]
L47  WCM2012F2SF-900T04  [CMLS-ACM2012]
Q15  MMFTN3019E  [SOT523]
R278  22R  [R0402L]
R282  NC/22R  [R0402L]
R284  NC/22R  [R0402L]
R286  22R  [R0402L]
R287  10K  [R0402L]
R288  22K  [R0402L]
R289  1.5K  [R0603L]
R290  NC/120R  [R1206L]
R291  22R  [R0402L]
R292  1.5K  [R0603L]
R293  10K  [R0402L]
R294  10K  [R0402L]
R295  22K  [R0402L]
R296  1.5K  [R0603L]
R297  NC/120R  [R1206L]
R298  1.5K  [R0603L]
R299  10K  [R0402L]
R300  0R  [R0402L]
R301  10K  [R0402L]
R302  2.2K  [R0402L]
R303  60.4R  [R0603L]
R304  60.4R  [R0603L]
R305  2.2K  [R0402L]
R306  10K  [R0402L]
R307  10K  [R0402L]
R308  2.2K  [R0402L]
R309  10K  [R0402L]
R310  60.4R  [R0603L]
R311  60.4R  [R0603L]
R367  0R  [R0402L]
R370  0R  [R0402L]
R371  0R  [R0402L]
R372  NC/0R  [R0402L]
R373  NC/0R  [R0402L]
R383  22R  [R0402L]
R384  NC/22R  [R0402L]
R385  NC/22R  [R0402L]
TP2  TP100  [smd_tp_1mm]
TP3  TP100  [smd_tp_1mm]
TP4  TP100  [smd_tp_1mm]
TP5  TP100  [smd_tp_1mm]
TP6  TP100  [smd_tp_1mm]
TP7  TP100  [smd_tp_1mm]
TP8  TP100  [smd_tp_1mm]
TP9  TP100  [smd_tp_1mm]
TP10  TP100  [smd_tp_1mm]
TP11  TP100  [smd_tp_1mm]
TP12  TP100  [smd_tp_1mm]
TP13  TP100  [smd_tp_1mm]
TP14  TP100  [smd_tp_1mm]
TP15  TP100  [smd_tp_1mm]
TP16  TP100  [smd_tp_1mm]
TP17  TP100  [smd_tp_1mm]
TP18  TP100  [smd_tp_1mm]
TP19  TP100  [smd_tp_1mm]
TP20  TP100  [smd_tp_1mm]
TP21  TP100  [smd_tp_1mm]
TP22  TP100  [smd_tp_1mm]
TP23  TP100  [smd_tp_1mm]
U26  SP3232EEY-L/TR  [SP3232EEY-TSSOP-16]
U27  SP3232EEY-L/TR  [SP3232EEY-TSSOP-16]
U28  MC74VHC1G04DFT2G  [SOT353]
U29  SP485EEN-L/TR  [SOP8-P127-390X490]
U30  MC74VHC1G04DFT2G  [SOT353]
U31  SP485EEN-L/TR  [SOP8-P127-390X490]
U32  TJA1044  [SOP8-P127-390X490]
U33  TJA1044  [SOP8-P127-390X490]

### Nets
GND: C217.1 C220.1 C221.1 C222.1 C225.1 C226.1 C227.1 C228.1 C229.1 C230.1 C231.1 C232.1 C233.1 C234.1 C235.1 C236.1 C237.1 C238.1 D78.3 D81.3 D85.3 D87.3 D89.3 D91.3 D103.3 J32.1 J32.5 J32.6 J33.1 J33.5 J33.6 J34.1 J34.5 J34.6 J35.1 J35.5 J35.6 J36.1 J36.5 J36.6 J39.3 J39.6 J39.7 R289.1 R293.2 R296.1 R299.2 R301.1 R307.1 TP16.1 TP17.1 TP18.1 TP19.1 TP20.1 TP21.1 TP22.1 TP23.1 U26.15(GND) U27.15(GND) U28.3(G) U29.5(GND) U30.3(G) U31.5(GND) U32.2(GND) U33.2(GND)
VCC5V0_SYS: C233.2 C236.2 D83.A J32.4 J33.4 J34.4 J35.4 J36.4 R306.1 R309.1 R367.1 U32.3(VCC) U33.3(VCC)
VCC_485: C228.2 C232.2 D83.C R292.2 R298.2 U29.8(VCC) U31.8(VCC)
VCCIO_WL: Q15.1(GATE) R305.1 R308.1
VDD_3V3: C217.2 C222.2 C229.2 C231.2 R287.1 R294.1 R300.1 R302.2 U26.16(VCC) U27.16(VCC) U28.5(V) U30.5(V)
CAN1_H: L46.1 U32.7(CANH)
CAN1_L: L46.2 U32.6(CANL)
CAN1_RX_M0: D90.A R302.1 ; off-sheet CAN1_RX_M0
CAN1_RX_M0_: D90.C U32.4(RXD)
CAN1_STB_IO: R301.2 U32.8(S)
CAN1_TX_M0: U32.1(TXD) ; off-sheet CAN1_TX_M0
CAN1H: D89.1 D105.A(I/O2) F10.1 L46.4 R304.1
CAN1H_: F10.2 J39.5 TP12.1
CAN1L: D89.2 D105.C(I/O1) F11.1 L46.3 R303.1
CAN1L_: F11.2 J39.4 TP13.1
CAN2_H: L47.1 U33.7(CANH)
CAN2_L: L47.2 U33.6(CANL)
CAN2_RX_M0: D107.A R305.2 ; off-sheet CAN2_RX_M0
CAN2_RX_M0_: D107.C R306.2 U33.4(RXD)
CAN2_STB_IO: R307.2 U33.8(S)
CAN2_TX_M0: Q15.2(SOURCE) R308.2 ; off-sheet CAN2_TX_M0
CAN2_TX_M0_: Q15.3(DRAIN) R309.2 U33.1(TXD)
CAN2H: D91.1 D106.A(I/O2) F12.1 L47.4 R311.1
CAN2H_: F12.2 J39.2 TP14.1
CAN2L: D91.2 D106.C(I/O1) F13.1 L47.3 R310.1
CAN2L_: F13.2 J39.1 TP15.1
RS485_5_DM: L42.1 R289.2 U29.7(B)
RS485_5_DP: L43.1 R292.1 U29.6(A)
RS485_5_RW_EN: R293.1 U28.4 U29.2(~{R}E) U29.3(DE)
RS485_7_DM: L44.1 R296.2 U31.7(B)
RS485_7_DP: L45.1 R298.1 U31.6(A)
RS485_7_RW_EN: R299.1 U30.4 U31.2(~{R}E) U31.3(DE)
S0RX: D103.2 F14.1 L41.2 R383.2
S0RX_: F14.2 J32.3 TP3.1
S0TX: D103.1 F15.1 L40.2 R278.2
S0TX_: F15.2 J32.2 TP2.1
S3RX_M1: D78.2 F2.1 L35.2 R384.2
S3RX_M1_: F2.2 J33.3 TP4.1
S3TX_M1: D78.1 F3.1 L34.2 R282.2
S3TX_M1_: F3.2 J33.2 TP5.1
S4RX_M1: D81.2 F4.1 L37.2 R385.2
S4RX_M1_: F4.2 J34.3 TP6.1
S4TX_M1: D81.1 F5.1 L36.2 R284.2
S4TX_M1_: F5.2 J34.2 TP7.1
S5RX_M1: D82.C U29.1(RO)
S5RX_M1/RS485-A5: D75.C(I/O1) D85.2 F6.1 L39.2 L43.2 R290.2
S5RX_M1_: F6.2 J35.3 TP8.1
S5TX_M1: R286.2 U29.4(DI)
S5TX_M1/RS485-B5: D75.A(I/O2) D85.1 F7.1 L38.2 L42.2 R290.1
S5TX_M1_: F7.2 J35.2 TP9.1
S7RX_M1: D86.C U31.1(RO)
S7RX_M1/RS485-A7: D87.2 D104.C(I/O1) F8.1 L45.2 R297.2
S7RX_M1_: F8.2 J36.3 TP10.1
S7TX_M1: R291.2 U31.4(DI)
S7TX_M1/RS485-B7: D87.1 D104.A(I/O2) F9.1 L44.2 R297.1
S7TX_M1_: F9.2 J36.2 TP11.1
UART0_RX: R372.1 R383.1 ; off-sheet UART0_RX  [project net PWM1_M0/GPUAVS/UART0_RX/GPIO0_C0_d]
UART0_RX_: R372.2 U27.9(R2OUT)
UART0_TX: R278.1 U27.10(T2IN) ; off-sheet UART0_TX  [project net PWM2_M0/NPUAVS/UART0_TX/MCU_JTAG_TDI/GPIO0_C1_d]
UART3_RX_M1: R370.1 R384.1 ; off-sheet UART3_RX_M1  [project net LCDC_D23/PWM13_M0/GMAC1_MCLKINOUT_M0/UART3_RX_M1/PDM_SDI3_M2/GPIO3_C0_d]
UART3_RX_M1_: R370.2 U26.12(R1OUT)
UART3_TX_M1: R282.1 U26.11(T1IN) ; off-sheet UART3_TX_M1  [project net LCDC_D22/PWM12_M0/GMAC1_TXEN_M0/UART3_TX_M1/PDM_SDI2_M2/GPIO3_B7_d]
UART4_RX_M1: R371.1 R385.1 ; off-sheet UART4_RX_M1  [project net LCDC_D16/VOP_BT1120_D7/GMAC1_RXD0_M0/UART4_RX_M1/PWM8_M0/GPIO3_B1_d]
UART4_RX_M1_: R371.2 U26.9(R2OUT)
UART4_TX_M1: R284.1 U26.10(T2IN) ; off-sheet UART4_TX_M1  [project net LCDC_D17/VOP_BT1120_D8/GMAC1_RXD1_M0/UART4_TX_M1/PWM9_M0/GPIO3_B2_d]
UART5_RX_M1: D82.A R287.2 R373.1 ; off-sheet UART5_RX_M1  [project net LCDC_DEN/VOP_BT1120_D15/SPI1_CLK_M1/UART5_RX_M1/I2S1_SCLK_RX_M2/GPIO3_C3_d]
UART5_RX_M1_: R373.2 U27.12(R1OUT)
UART5_TX_M1: D84.C R286.1 R288.1 U27.11(T1IN) ; off-sheet UART5_TX_M1  [project net LCDC_VSYNC/VOP_BT1120_D14/SPI1_MISO_M1/UART5_TX_M1/I2S1_SDO3_M2/GPIO3_C2_d]
UART7_RX_M1: D86.A R294.2 ; off-sheet UART7_RX_M1  [project net PWM15_IR_M0/SPDIF_TX_M1/GMAC1_MDIO_M0/UART7_RX_M1/I2S1_LRCK_RX_M2/GPIO3_C5_d]
UART7_TX_M1: D88.C R291.1 R295.1 ; off-sheet UART7_TX_M1  [project net PWM14_M0/VOP_PWM_M1/GMAC1_MDC_M0/UART7_TX_M1/PDM_CLK1_M2/GPIO3_C4_d]
NetC218_1: C218.1 U26.3(C1-)
NetC218_2: C218.2 U26.1(C1+)
NetC219_1: C219.1 U26.5(C2-)
NetC219_2: C219.2 U26.4(C2+)
NetC220_2: C220.2 U26.2(V+)
NetC221_2: C221.2 U26.6(V-)
NetC223_1: C223.1 U27.3(C1-)
NetC223_2: C223.2 U27.1(C1+)
NetC224_1: C224.1 U27.5(C2-)
NetC224_2: C224.2 U27.4(C2+)
NetC225_2: C225.2 U27.2(V+)
NetC226_2: C226.2 U27.6(V-)
NetC227_2: C227.2 D84.A R288.2 U28.2
NetC230_2: C230.2 D88.A R295.2 U30.2
NetC234_2: C234.2 R300.2 U32.5(VIO/NC)
NetC235_2: C235.2 R303.2 R304.2
NetC237_2: C237.2 R367.2 U33.5(VIO/NC)
NetC238_2: C238.2 R310.2 R311.2
NetL34_1: L34.1 U26.14(T1OUT)
NetL35_1: L35.1 U26.13(R1IN)
NetL36_1: L36.1 U26.7(T2OUT)
NetL37_1: L37.1 U26.8(R2IN)
NetL38_1: L38.1 U27.14(T1OUT)
NetL39_1: L39.1 U27.13(R1IN)
NetL40_1: L40.1 U27.7(T2OUT)
NetL41_1: L41.1 U27.8(R2IN)

Not connected (* = marked no-connect by the designer): U28 1(NC); U30 1(NC)

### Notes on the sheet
- UART
- RS232-3
- 3.3V
- 1.8V
- RS232-4
- RS485-5
- RS485-7
- CAN1_M0
- CAN2_M0

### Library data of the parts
C217 C219 C223 C225 C226 = C-0402_Dup1: Manufacture: 三星¦国巨¦村田; Part Name: 贴片电容; Part Number: C020102120061; PCB Footprint: C0402L; ID: 61; DSC3: X7R; DSC1: ±10%; ERP Number: 1010200128
C218 C220-C222 C224 C235 C238 = C-0402_Dup1: Part Number: C020102120061; Part Name: 贴片电容; Manufacture: 三星¦国巨¦村田; PCB Footprint: C0402L; ERP Number: 1010200128; DSC1: ±10%; DSC3: X7R; ID: 61
C227 C230 = C-0402_Dup1: Manufacture: 三星¦国巨¦村田; Part Name: 贴片电容; Part Number: C020102120054; ID: 54; DSC3: X7R; DSC1: ±10%; ERP Number: 1010200084; PCB Footprint: C0402L
C228 C232 C233 C236 = C-0402_Dup1: as C161 on sheet P17
C229 C231 = C-0402_Dup1: as C145 on sheet P16
C234 C237 = C-0402_Dup1: as C162 on sheet P17
D75 = DI-TVS-D: ESD 0402; Part Number: C040602260005; Manufacture P/N: MLVG04021R0UV18; Manufacturer: INPAQ; Manufacture: MDD¦伯恩半导体; Part Name: TVS; PN Type: Varistor; ID: 5; DSC6: Ppp=400W; DSC5: Ipp=20.1A; DSC4: Vc=19.9V; DSC3: VBR=13.3V; DSC2: Vrwm=12V; DSC1: 双向; ERP Number: 1010800028
D78 D81 D85 D87 D103 = DI-TVS-BST23A122V: Part Number: C040602260019; Part Name: TVS; Manufacture: 伯恩半导体; DSC1: 单向; DSC2: Vrwm=12V; DSC3: VBR=13.3V; DSC4: Vc=25V; DSC5: Ipp=12A; DSC6: Ppp=300W; DSC7: Cj=150pF; ID: 19; Solder: 推荐
D82 D86 D107 = DI-XI-S: Manufacture: 乐山无线电; Part Name: 肖特基二级管; Part Number: C040202220002; CLASS: IC; Solder: 推荐; ID: 2; DSC4: IR=0.5uA; DSC3: VF=350mV/10mA; DSC2: IF=200mA; DSC1: VR=30V
D83 = DI-XI-S: Part Number: C040202220005; Part Name: 肖特基二级管; Manufacture: 长电; CLASS: IC; DSC1: VR=40V; DSC2: IF=1A; DSC3: VF=600mV/1A; DSC4: IR=1mA; ID: 5
D84 D88 D90 = DI-XI-S: Part Number: C040202220002; Part Name: 肖特基二级管; Manufacture: 乐山无线电; CLASS: IC; DSC1: VR=30V; DSC2: IF=200mA; DSC3: VF=350mV/10mA; DSC4: IR=0.5uA; ID: 2; Solder: 推荐
D89 D91 = DI-TVS-BST23A122V: Manufacture: 伯恩半导体; Part Name: TVS; Part Number: C040602260019; Solder: 推荐; ID: 19; DSC7: Cj=150pF; DSC6: Ppp=300W; DSC5: Ipp=12A; DSC4: Vc=25V; DSC3: VBR=13.3V; DSC2: Vrwm=12V; DSC1: 单向
D104-D106 = DI-TVS-D: ESD 0402; Part Number: C040602260005; Manufacture P/N: MLVG04021R0UV18; Manufacturer: INPAQ; Part Name: TVS; Manufacture: MDD¦伯恩半导体; PN Type: Varistor; ERP Number: 1010800028; DSC1: 双向; DSC2: Vrwm=12V; DSC3: VBR=13.3V; DSC4: Vc=19.9V; DSC5: Ipp=20.1A; DSC6: Ppp=400W; ID: 5
F2-F9 F14 F15 = FUSE-SMD1206: Part Number: C160102670005; Part Name: 自恢复保险丝; Manufacture: BOURNS¦金科; DSC1: 60V; DSC2: 0.1A; DSC3: SMD1206P010TF; DSC4: JK-NSMD010; ID: 5
F10-F13 = FUSE-SMD1206: Manufacture: BOURNS¦金科; Part Name: 自恢复保险丝; Part Number: C160102670005; ID: 5; DSC4: JK-NSMD010; DSC3: SMD1206P010TF; DSC2: 0.1A; DSC1: 60V
J32 J34 J36 = J-A-4P: Part Name: PH; Part Number: J020302820060; ID: 28; DSC5: A2001WR-S-4P(CJT); DSC4: 米黄色胶壳 耐高温; DSC3: 卧贴; DSC2: 2.0mm间距; DSC1: 4p
J33 J35 = J-A-4P: Part Number: J020302820060; Part Name: PH; DSC1: 4p; DSC2: 2.0mm间距; DSC3: 卧贴; DSC4: 米黄色胶壳 耐高温; DSC5: A2001WR-S-4P(CJT); ID: 28
J39 = J-A-5P: Part Name: PH; Part Number: J020302820061; ID: 29; DSC5: A2001WR-S-5P(CJT); DSC4: 米黄色胶壳 耐高温; DSC3: 卧贴; DSC2: 2.0mm间距; DSC1: 5p
L34-L41 = FB-0402: SMD Multilayer Ferrite Chip Bead,3A,30Ohm,0.03R; Part Number: C060502370001; Manufacture P/N: PZ1608D300-3R0TF; Manufacture2 P/N: PBY160808T-400Y-N; Manufacturer: SUNLORD; Part Name: 贴片磁珠; Manufacture: 顺络; PN Type: SMD FERRITE BEAD; ERP Number: 1010200208; DSC1: 120Ω@100MHz; DSC2: 200mA; DSC3: DCR=400mΩ; DSC4: 低频信号; ID: 1
L42-L45 = FB-0402: SMD Multilayer Ferrite Chip Bead,3A,30Ohm,0.03R; Part Number: C060502370001; Manufacture P/N: PZ1608D300-3R0TF; Manufacture2 P/N: PBY160808T-400Y-N; Manufacturer: SUNLORD; Manufacture: 顺络; Part Name: 贴片磁珠; PN Type: SMD FERRITE BEAD; ID: 1; DSC4: 低频信号; DSC3: DCR=400mΩ; DSC2: 200mA; DSC1: 120Ω@100MHz; ERP Number: 1010200208
L46 L47 = L-CMLS-ACM2012: Part Name: 信号共模电感; Part Number: C060402360001; Manufacture: 台庆; ERP Number: 1010200196; DSC1: 90uH@100kHz; DSC2: 90Ω@100MHz; DSC3: 400mA; DSC4: DCR=300mΩ; DSC5: -40℃ ~ +125℃; DSC6: SMD_4P,2x1.2mm; ID: 1
Q15 = N-MOS-Q: Part Number: C030202190004; Part Name: N-MOS; Manufacture: 先科; ERP Number: 1010800011; DSC1: Vds=30V; DSC2: Id=100mA; DSC3: Vgs(th)=1.5V; DSC4: Vgs=±20V; DSC5: pd=150mW; ID: 4
R278 R286 R291 = R-0402_Dup1: as R144 on sheet P16
R282 R284 R383-R385 = R-0402_Dup1: as R143 on sheet P16
R287 R293 R294 R299 = R-0402_Dup1: as R148-R151 on sheet P16
R288 R295 = R-0402_Dup1: Part Name: 贴片电阻; Part Number: C011002080893; DSC1: ±1%; DSC2: 1/16W; ID: 893
R289 R296 = R-0603: Part Name: 贴片电阻; Part Number: C011002081416; DSC1: ±1%; DSC2: 1/10W; ID: 1,416
R290 R297 = R-1206: Part Number: C011002081999; Part Name: 贴片电阻; ID: 1,999; DSC2: 1/4W; DSC1: ±1%; ERP Number: 1010200271
R292 R298 = R-0603: Part Number: C011002081416; Part Name: 贴片电阻; ID: 1,416; DSC2: 1/10W; DSC1: ±1%
R300 R367 = R-0402_Dup1: as R142 on sheet P16
R301 R306 R307 R309 = R-0402_Dup1: as R173 on sheet P17
R302 R305 R308 = R-0402_Dup1: as R147 on sheet P16
R303 R304 R310 R311 = R-0603: Part Number: C011002081339; Part Name: 贴片电阻; ID: 1,339; DSC2: 1/10W; DSC1: ±1%
R370-R373 = R-0402_Dup1: as R132-R141 on sheet P16
TP2 TP4 TP6 TP8 TP10 = TP-TEST: Part Number: CAD; Part Name: 测试点; DSC1: 焊盘1mm; DSC2: 无孔; DSC3: 圆形; DSC4: 单面; ID: 3
TP3 TP5 TP7 TP9 TP11-TP23 = TP-TEST: Part Number: CAD; Part Name: 测试点; ID: 3; DSC4: 单面; DSC3: 圆形; DSC2: 无孔; DSC1: 焊盘1mm
U26 = U-SP3232EEN-L-TR: Part Number: C100308133921; Part Name: RS232/RS485芯片; Manufacture: EXAR(艾科嘉); DSC1: RS232 Transceiver up to 235kbps; DSC2: TSSOP-16，0.65mm Pitch; DSC3: -40℃~+85℃; ID: 49
U27 = U-SP3232EEN-L-TR: Manufacture: EXAR(艾科嘉); Part Name: RS232/RS485芯片; Part Number: C100308133921; ID: 49; DSC3: -40℃~+85℃; DSC2: TSSOP-16，0.65mm Pitch; DSC1: RS232 Transceiver up to 235kbps
U28 U30 = U-MC74VHC1G04DFT2G: Manufacture: ON 安森美; Part Number: C080102450001; Part Name: 逻辑芯片; ID: 1; DSC3: -55℃~+125℃; DSC2: SOT?353; DSC1: 1位 反向 VCC=2V-5.5V; ERP Number: 1010100124
U29 U31 = U-SP485EEN-L-TR: Part Number: C100302510003; Part Name: RS232/RS485芯片; Manufacture: EXAR(艾科嘉); ERP Number: 1010100125; DSC1: RS485 Transceiver ,up to 10Mbps; DSC2: SOIC-8_150mil，1.27mm Pitch; DSC3: -40℃~+85℃; ID: 24
U32 U33 = U-TJA1057GT-3J: Part Number: C100402520002; Part Name: CAN芯片; Manufacture: NXP; ERP Number: 1010100240; DSC1: CAN Transceiver, 5Mbps; DSC2: SOIC-8_150mil，1.27mm Pitch; DSC3: -40℃~+150℃; ID: 27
